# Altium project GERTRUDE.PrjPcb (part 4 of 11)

## Sheet USB.SchDoc: USB
size A3; Author: Silvio Navaretti; CompanyName: ARDUINO; DrawnBy: Silvio Navaretti; Engineer: Silvio Navaretti; Organization: ARDUINO; SheetNumber: 30; SheetTotal: 51; RevAuthor: Silvio Navaretti
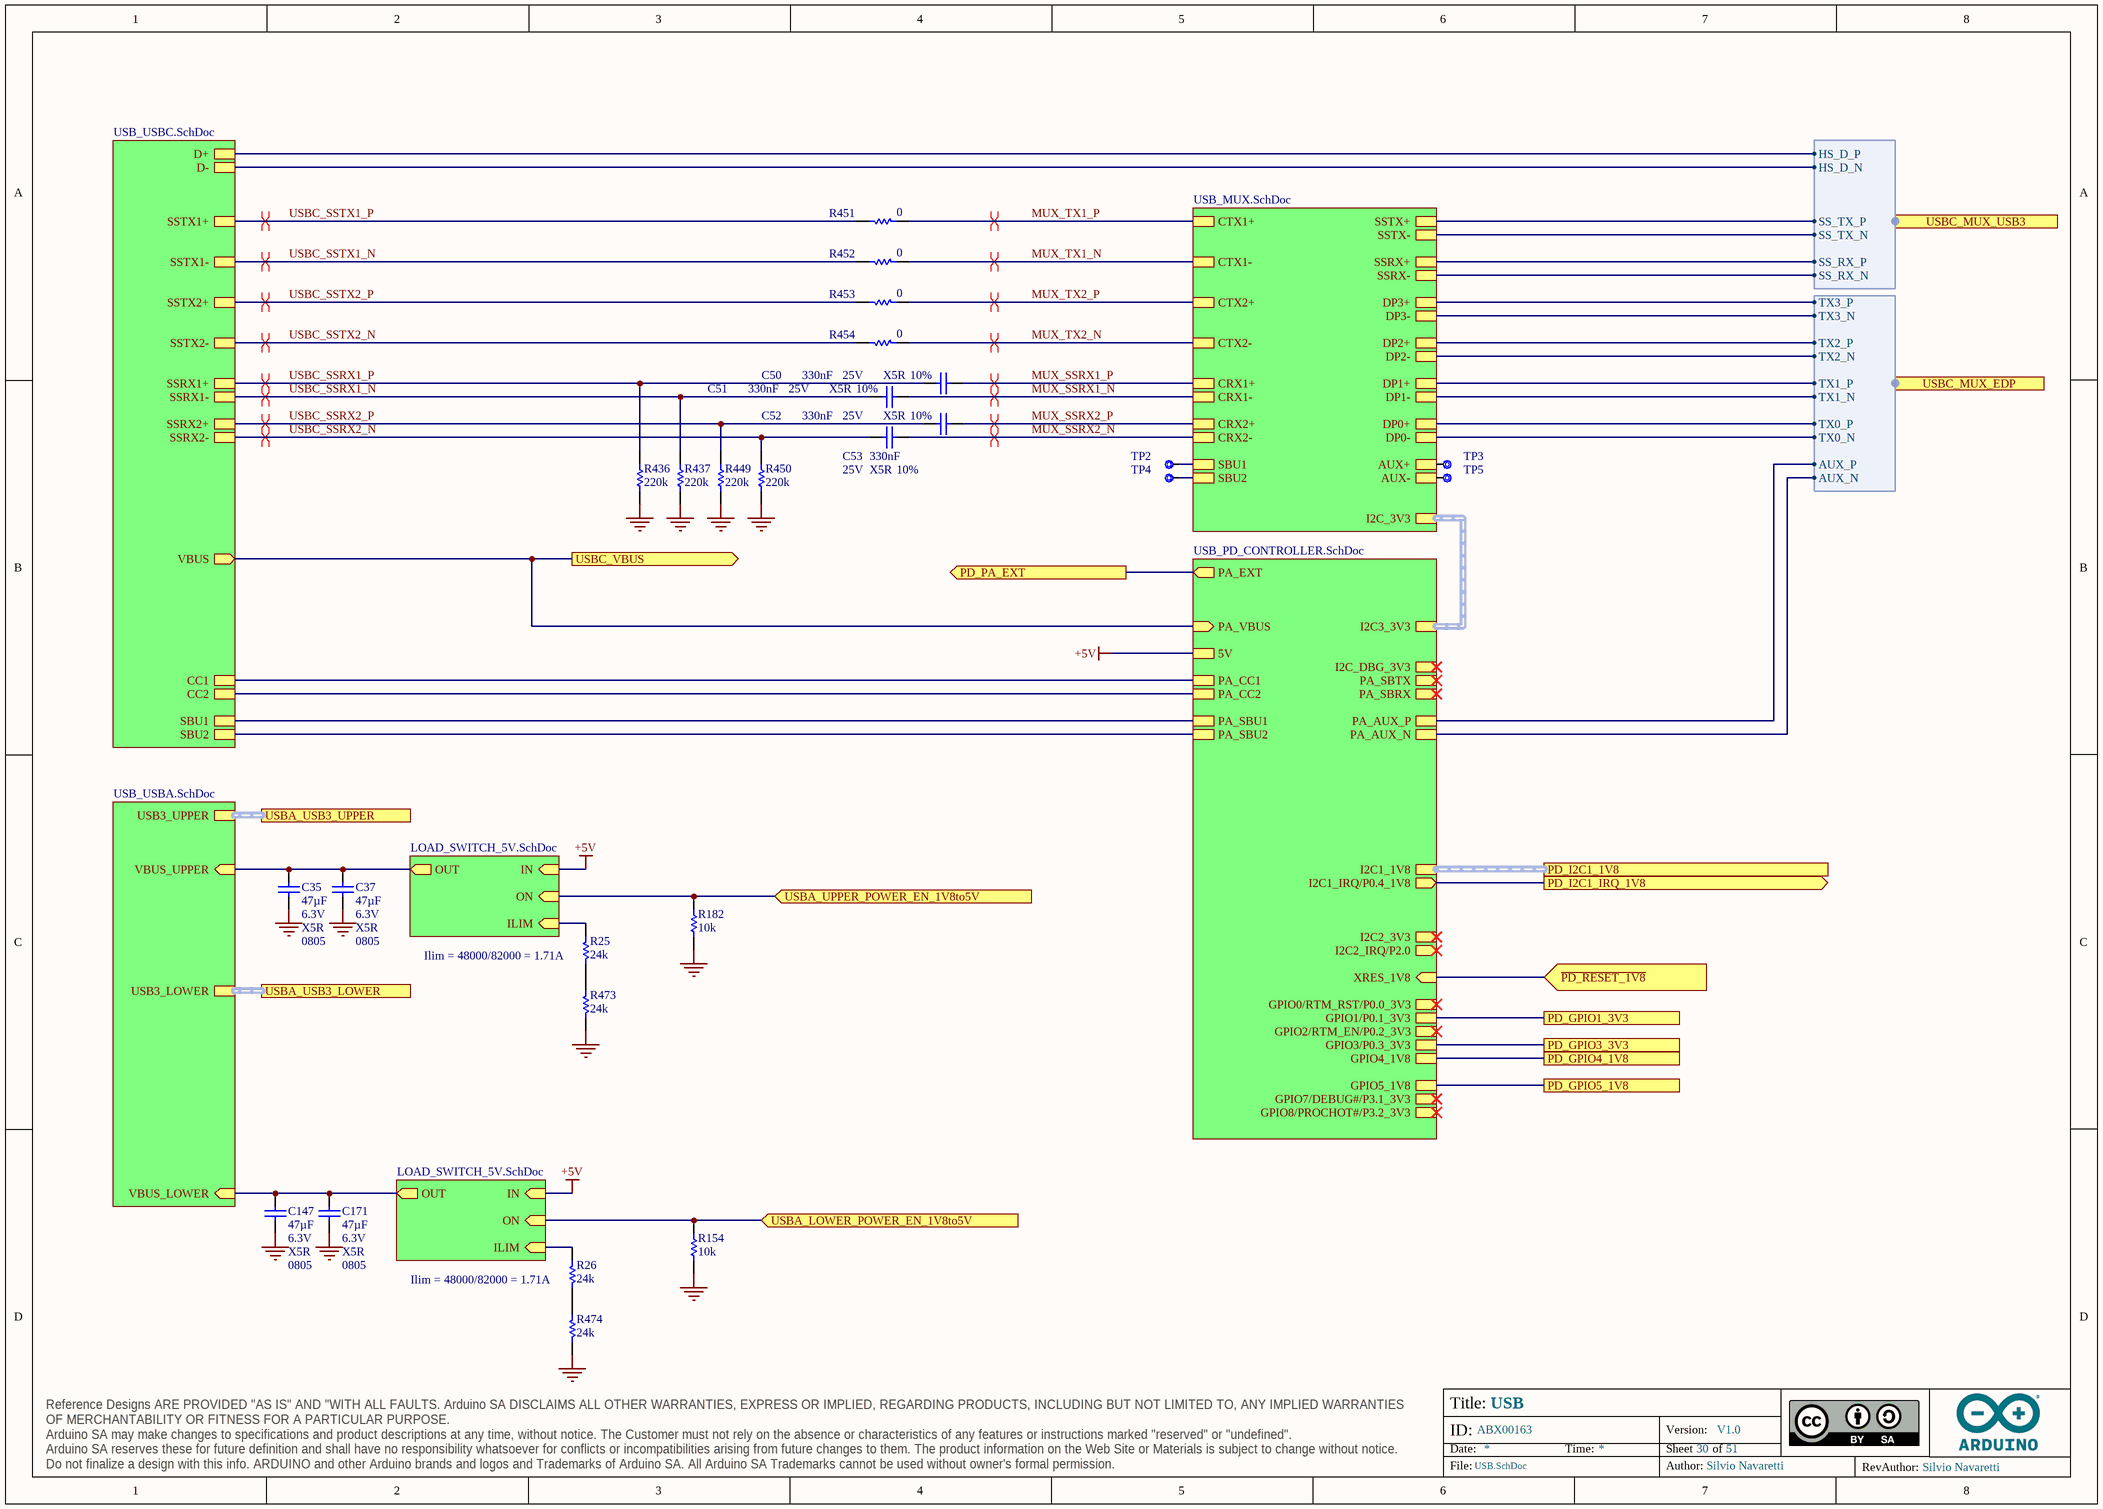
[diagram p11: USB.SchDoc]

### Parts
C35  value 47µF  Voltage: 6.3V  Dielectric: X5R  Case Code (Imperial): 0805  [CAP-0805]  (hidden comment: C0805C476M9PAC7800)
C37  value 47µF  Voltage: 6.3V  Dielectric: X5R  Case Code (Imperial): 0805  [CAP-0805]  (hidden comment: C0805C476M9PAC7800)
C50  value 330nF  Voltage: 25V  Dielectric: X5R  Tolerance: 10%  [CAP-0201]  (hidden comment: CL03A334KA3NRNC)
C51  value 330nF  Voltage: 25V  Dielectric: X5R  Tolerance: 10%  [CAP-0201]  (hidden comment: CL03A334KA3NRNC)
C52  value 330nF  Voltage: 25V  Dielectric: X5R  Tolerance: 10%  [CAP-0201]  (hidden comment: CL03A334KA3NRNC)
C53  value 330nF  Voltage: 25V  Dielectric: X5R  Tolerance: 10%  [CAP-0201]  (hidden comment: CL03A334KA3NRNC)
C147  value 47µF  Voltage: 6.3V  Dielectric: X5R  Case Code (Imperial): 0805  [CAP-0805]  (hidden comment: C0805C476M9PAC7800)
C171  value 47µF  Voltage: 6.3V  Dielectric: X5R  Case Code (Imperial): 0805  [CAP-0805]  (hidden comment: C0805C476M9PAC7800)
R25  value 24k  [RES-0201]  (hidden comment: RC0201FR-0724KL)
R26  value 24k  [RES-0201]  (hidden comment: RC0201FR-0724KL)
R154  value 10k  [RES-0201]  (hidden comment: RC0201FR-0710KL)
R182  value 10k  [RES-0201]  (hidden comment: RC0201FR-0710KL)
R436  value 220k  [RES-0201]  (hidden comment: AC0201FR-07220KL)
R437  value 220k  [RES-0201]  (hidden comment: AC0201FR-07220KL)
R449  value 220k  [RES-0201]  (hidden comment: AC0201FR-07220KL)
R450  value 220k  [RES-0201]  (hidden comment: AC0201FR-07220KL)
R451  value 0  [RES-0201]  (hidden comment: CRCW02010000Z0ED)
R452  value 0  [RES-0201]  (hidden comment: CRCW02010000Z0ED)
R453  value 0  [RES-0201]  (hidden comment: CRCW02010000Z0ED)
R454  value 0  [RES-0201]  (hidden comment: CRCW02010000Z0ED)
R473  value 24k  [RES-0201]  (hidden comment: RC0201FR-0724KL)
R474  value 24k  [RES-0201]  (hidden comment: RC0201FR-0724KL)
TP2  Test point 1.00mm  [TP-1.00MM]  (value not drawn)  (no BOM)
TP3  Test point 1.00mm  [TP-1.00MM]  (value not drawn)  (no BOM)
TP4  Test point 1.00mm  [TP-1.00MM]  (value not drawn)  (no BOM)
TP5  Test point 1.00mm  [TP-1.00MM]  (value not drawn)  (no BOM)

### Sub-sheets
U_LOAD_SWITCH_5V = LOAD_SWITCH_5V.SchDoc: IN (in), OUT (out), ON (in), ILIM (in)
U_LOAD_SWITCH_5V = LOAD_SWITCH_5V.SchDoc: IN (in), OUT (out), ON (in), ILIM (in)
U_USB_MUX = USB_MUX.SchDoc: I2C_3V3 (harness I2C), SSTX-, SSTX+, SBU1, SBU2, SSRX-, SSRX+, DP3+, DP3-, DP2+, DP2-, DP1+, DP1-, DP0+, DP0-, AUX+, AUX-, CTX2+, CTX2-, CRX2+, CRX2-, CRX1+, CRX1-, CTX1+, CTX1-
U_USB_PD_CONTROLLER = USB_PD_CONTROLLER.SchDoc: 5V, PA_VBUS (in), PA_EXT (out), PA_SBU2, PA_SBU1, PA_CC2, PA_CC1, PA_SBTX, PA_SBRX, PA_AUX_P, PA_AUX_N, I2C2_IRQ/P2.0 (out), I2C2_3V3 (harness I2C), I2C3_3V3 (harness I2C), I2C_DBG_3V3 (harness I2C), GPIO0/RTM_RST/P0.0_3V3, GPIO1/P0.1_3V3, GPIO2/RTM_EN/P0.2_3V3, GPIO3/P0.3_3V3, GPIO7/DEBUG#/P3.1_3V3, GPIO8/PROCHOT#/P3.2_3V3, GPIO4_1V8, GPIO5_1V8, I2C1_IRQ/P0.4_1V8 (out), I2C1_1V8 (harness I2C), XRES_1V8 (in)
U_USB_USBA = USB_USBA.SchDoc: VBUS_LOWER (in), USB3_LOWER (harness SOM_MD_USB0), VBUS_UPPER (in), USB3_UPPER (harness SOM_MD_USB0)
U_USB_USBC = USB_USBC.SchDoc: D-, D+, CC1, CC2, SSTX2-, SSTX2+, SSTX1-, SSTX1+, VBUS (out), SBU1, SBU2, SSRX2-, SSRX2+, SSRX1-, SSRX1+

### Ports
PD_GPIO1_3V3, PD_GPIO3_3V3, PD_GPIO4_1V8, PD_GPIO5_1V8, PD_I2C1_1V8 (harness I2C), PD_I2C1_IRQ_1V8 (out), PD_PA_EXT (out), USBA_LOWER_POWER_EN_1V8to5V (in), USBA_UPPER_POWER_EN_1V8to5V (in), USBA_USB3_LOWER (harness SOM_MD_EDP0), USBA_USB3_UPPER (harness SOM_MD_EDP0), USBC_MUX_EDP (harness SOM_MD_EDP0), USBC_MUX_USB3 (harness SOM_MD_USB0), USBC_VBUS (out), ~{PD_RESET_1V8} (in)

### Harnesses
SOM_MD_USB0: SS_TX_N, SS_TX_P, HS_D_P, HS_D_N, SS_RX_P, SS_RX_N
SOM_MD_EDP0: TX0_P, TX1_P, TX2_P, TX3_P, AUX_P, TX0_N, TX1_N, TX2_N, TX3_N, AUX_N

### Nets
+5V: sheet U_USB_PD_CONTROLLER/5V, sheet U_LOAD_SWITCH_5V/IN, sheet U_LOAD_SWITCH_5V/IN
GND: C35.1 C37.1 C147.1 C171.1 R154.1 R182.1 R436.2 R437.2 R449.2 R450.2 R473.1 R474.1
EDP0_AUX_N: sheet U_USB_PD_CONTROLLER/PA_AUX_N, port USBC_MUX_EDP.AUX_N
EDP0_AUX_P: sheet U_USB_PD_CONTROLLER/PA_AUX_P, port USBC_MUX_EDP.AUX_P
EDP0_TX0_N: sheet U_USB_MUX/DP0-, port USBC_MUX_EDP.TX0_N
EDP0_TX0_P: sheet U_USB_MUX/DP0+, port USBC_MUX_EDP.TX0_P
EDP0_TX1_N: sheet U_USB_MUX/DP1-, port USBC_MUX_EDP.TX1_N
EDP0_TX1_P: sheet U_USB_MUX/DP1+, port USBC_MUX_EDP.TX1_P
EDP0_TX2_N: sheet U_USB_MUX/DP2-, port USBC_MUX_EDP.TX2_N
EDP0_TX2_P: sheet U_USB_MUX/DP2+, port USBC_MUX_EDP.TX2_P
EDP0_TX3_N: sheet U_USB_MUX/DP3-, port USBC_MUX_EDP.TX3_N
EDP0_TX3_P: sheet U_USB_MUX/DP3+, port USBC_MUX_EDP.TX3_P
MD_GPIO_3: port PD_I2C1_IRQ_1V8, sheet U_USB_PD_CONTROLLER/I2C1_IRQ/P0.4_1V8
MD_GPIO_48: port PD_GPIO5_1V8, sheet U_USB_PD_CONTROLLER/GPIO5_1V8
MD_GPIO_94: port PD_GPIO4_1V8, sheet U_USB_PD_CONTROLLER/GPIO4_1V8
MD_GPIO_104: port ~{PD_RESET_1V8}, sheet U_USB_PD_CONTROLLER/XRES_1V8
MD_USB0_3.1.HS_D_N: sheet U_USB_USBC/D-, port USBC_MUX_USB3.HS_D_N
MD_USB0_3.1.HS_D_P: sheet U_USB_USBC/D+, port USBC_MUX_USB3.HS_D_P
MD_USB0_3.1.SS_RX_N: sheet U_USB_MUX/SSRX-, port USBC_MUX_USB3.SS_RX_N
MD_USB0_3.1.SS_RX_P: sheet U_USB_MUX/SSRX+, port USBC_MUX_USB3.SS_RX_P
MD_USB0_3.1.SS_TX_N: sheet U_USB_MUX/SSTX-, port USBC_MUX_USB3.SS_TX_N
MD_USB0_3.1.SS_TX_P: sheet U_USB_MUX/SSTX+, port USBC_MUX_USB3.SS_TX_P
MUX_SSRX1_N: C51.1 ; sheet U_USB_MUX/CRX1-
MUX_SSRX1_P: C50.1 ; sheet U_USB_MUX/CRX1+
MUX_SSRX2_N: C53.1 ; sheet U_USB_MUX/CRX2-
MUX_SSRX2_P: C52.1 ; sheet U_USB_MUX/CRX2+
MUX_TX1_N: R452.2 ; sheet U_USB_MUX/CTX1-
MUX_TX1_P: R451.2 ; sheet U_USB_MUX/CTX1+
MUX_TX2_N: R454.2 ; sheet U_USB_MUX/CTX2-
MUX_TX2_P: R453.2 ; sheet U_USB_MUX/CTX2+
PA_VBUS: port USBC_VBUS, sheet U_USB_USBC/VBUS, sheet U_USB_PD_CONTROLLER/PA_VBUS
USBC_CC1: sheet U_USB_USBC/CC1, sheet U_USB_PD_CONTROLLER/PA_CC1
USBC_CC2: sheet U_USB_USBC/CC2, sheet U_USB_PD_CONTROLLER/PA_CC2
USBC_SBU1: sheet U_USB_USBC/SBU1, sheet U_USB_PD_CONTROLLER/PA_SBU1
USBC_SBU2: sheet U_USB_USBC/SBU2, sheet U_USB_PD_CONTROLLER/PA_SBU2
USBC_SSRX1_N: C51.2 R437.1 ; sheet U_USB_USBC/SSRX1-
USBC_SSRX1_P: C50.2 R436.1 ; sheet U_USB_USBC/SSRX1+
USBC_SSRX2_N: C53.2 R450.1 ; sheet U_USB_USBC/SSRX2-
USBC_SSRX2_P: C52.2 R449.1 ; sheet U_USB_USBC/SSRX2+
USBC_SSTX1_N: R452.1 ; sheet U_USB_USBC/SSTX1-
USBC_SSTX1_P: R451.1 ; sheet U_USB_USBC/SSTX1+
USBC_SSTX2_N: R454.1 ; sheet U_USB_USBC/SSTX2-
USBC_SSTX2_P: R453.1 ; sheet U_USB_USBC/SSTX2+
NetC35_2: C35.2 C37.2 ; sheet U_USB_USBA/VBUS_UPPER, sheet U_LOAD_SWITCH_5V/OUT
NetC147_2: C147.2 C171.2 ; sheet U_USB_USBA/VBUS_LOWER, sheet U_LOAD_SWITCH_5V/OUT
NetQ3_2: port PD_GPIO3_3V3, sheet U_USB_PD_CONTROLLER/GPIO3/P0.3_3V3
NetQ3_3: port PD_GPIO1_3V3, sheet U_USB_PD_CONTROLLER/GPIO1/P0.1_3V3
NetR25_1: R25.1 R473.2
NetR25_2: R25.2 ; sheet U_LOAD_SWITCH_5V/ILIM
NetR26_1: R26.1 R474.2
NetR26_2: R26.2 ; sheet U_LOAD_SWITCH_5V/ILIM
NetR154_2: R154.2 ; port USBA_LOWER_POWER_EN_1V8to5V, sheet U_LOAD_SWITCH_5V/ON
NetR182_2: R182.2 ; port USBA_UPPER_POWER_EN_1V8to5V, sheet U_LOAD_SWITCH_5V/ON
NetR215_1: port PD_PA_EXT, sheet U_USB_PD_CONTROLLER/PA_EXT
NetTP2_X: TP2.X ; sheet U_USB_MUX/SBU1
NetTP3_X: TP3.X ; sheet U_USB_MUX/AUX+
NetTP4_X: TP4.X ; sheet U_USB_MUX/SBU2
NetTP5_X: TP5.X ; sheet U_USB_MUX/AUX-

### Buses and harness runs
harness port PD_I2C1_1V8 = sheet U_USB_PD_CONTROLLER/I2C1_1V8
harness port USBA_USB3_LOWER = sheet U_USB_USBA/USB3_LOWER
harness port USBA_USB3_UPPER = sheet U_USB_USBA/USB3_UPPER
harness sheet U_USB_MUX/I2C_3V3 = sheet U_USB_PD_CONTROLLER/I2C3_3V3

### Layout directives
differential pair; differential pair class DIFF_MUX_USBC; net class NET_DIFF_USBC: MUX_SSRX1_N, MUX_SSRX1_P, MUX_SSRX2_N, MUX_SSRX2_P, MUX_TX1_N, MUX_TX1_P, MUX_TX2_N, MUX_TX2_P
differential pair; differential pair class DIFF_MUXCAPS_USBC; net class NET_DIFF_USB: USBC_SSRX1_N, USBC_SSRX1_P, USBC_SSRX2_N, USBC_SSRX2_P, USBC_SSTX1_N, USBC_SSTX1_P, USBC_SSTX2_N, USBC_SSTX2_P

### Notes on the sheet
- (near R25) Ilim = 48000/82000 = 1.71A
- (near R26) Ilim = 48000/82000 = 1.71A

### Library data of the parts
C35 C37 C147 C171 = C0199-A.1: CAP CHIP 0805 47uF 20% 6.3V X5R; Manufacturer: KEMET; Code Arduino: C0199
C50-C53 = C0201-A.1: CAP CHIP 0201 330nF 10% 25V X5R; Manufacturer: Samsung Electro-Mechanics; Code Arduino: C0201
R25 R26 R473 R474 = R0398-A.1: RES CHIP 0201 24k 1% 1/20W; Manufacturer: YAGEO; Power: 50mW; Code Arduino: R0398; Temperature Coefficient: 200ppm
R154 R182 = R0145-A.21: RES CHIP 0201 10k 1% 1/20W; Manufacturer: Yageo; Power: 50mW; Temperature coefficient: 200ppm; Code Arduino: R0145
R436 R437 R449 R450 = R0199-A.20: RES CHIP 0201 220k 1% 1/20W; Manufacturer: Yageo; Temperature coefficient: 200ppm; Power: 50mW; Code Arduino: R0199
R451-R454 = R0140-A.21: RES CHIP 0201 0R; Manufacturer: Vishay; Tolerance: 0%; Code Arduino: R0140; Temperature coefficient: 0ppm; Power: 50mW
TP2-TP5 = UT0013-A.6: Part Number: This is not a component

## Sheet USB_USBC.SchDoc: USBC
size A3; Author: Silvio Navaretti; CompanyName: ARDUINO; DrawnBy: Silvio Navaretti; Engineer: Silvio Navaretti; Organization: ARDUINO; SheetNumber: 31; SheetTotal: 51; RevAuthor: Silvio Navaretti
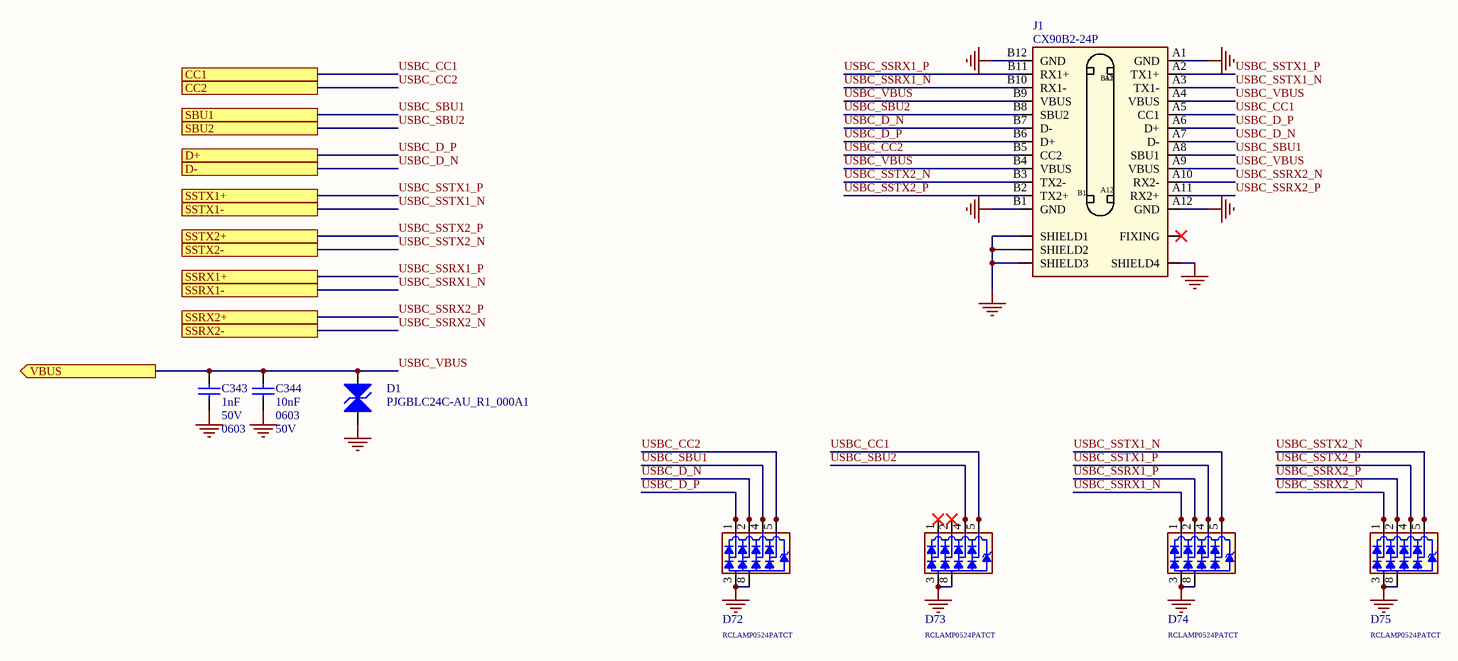
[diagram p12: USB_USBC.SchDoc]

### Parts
C343  value 1nF  Voltage: 50V  Case Code (Imperial): 0603  [CAP-0603]  (hidden comment: CL10B102KB8WPNC)
C344  value 10nF  Case Code (Imperial): 0603  Voltage: 50V  [CAP-0603]  (hidden comment: 0603B103K500CT)
D1  PJGBLC24C-AU_R1_000A1  [SOD323 NO POLARITY]
D72  RCLAMP0524PATCT  [SLP2510P8]
D73  RCLAMP0524PATCT  [SLP2510P8]
D74  RCLAMP0524PATCT  [SLP2510P8]
D75  RCLAMP0524PATCT  [SLP2510P8]
J1  CX90B2-24P  [CX90B2-24P]

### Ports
CC1, CC2, D+, D-, SBU1, SBU2, SSRX1+, SSRX1-, SSRX2+, SSRX2-, SSTX1+, SSTX1-, SSTX2+, SSTX2-, VBUS (out)

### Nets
GND: C343.2 C344.2 D1.1(A1) D72.3 D72.8 D73.3 D73.8 D74.3 D74.8 D75.3 D75.8 J1.A1(GND) J1.A12(GND) J1.B1(GND) J1.B12(GND) J1.SHIELD1 J1.SHIELD2 J1.SHIELD3 J1.SHIELD4
USBC_CC1: D73.5 D73.6 J1.A5(CC1) ; port CC1
USBC_CC2: D72.5 D72.6 J1.B5(CC2) ; port CC2
USBC_D_N: D72.2 D72.9 J1.A7(D-) J1.B7(D-) ; port D-  [project net MD_USB0_3.1.HS_D_N]
USBC_D_P: D72.1 D72.10 J1.A6(D+) J1.B6(D+) ; port D+  [project net MD_USB0_3.1.HS_D_P]
USBC_SBU1: D72.4 D72.7 J1.A8(SBU1) ; port SBU1
USBC_SBU2: D73.4 D73.7 J1.B8(SBU2) ; port SBU2
USBC_SSRX1_N: D74.1 D74.10 J1.B10(RX1-) ; port SSRX1-
USBC_SSRX1_P: D74.2 D74.9 J1.B11(RX1+) ; port SSRX1+
USBC_SSRX2_N: D75.1 D75.10 J1.A10(RX2-) ; port SSRX2-
USBC_SSRX2_P: D75.2 D75.9 J1.A11(RX2+) ; port SSRX2+
USBC_SSTX1_N: D74.5 D74.6 J1.A3(TX1-) ; port SSTX1-
USBC_SSTX1_P: D74.4 D74.7 J1.A2(TX1+) ; port SSTX1+
USBC_SSTX2_N: D75.5 D75.6 J1.B3(TX2-) ; port SSTX2-
USBC_SSTX2_P: D75.4 D75.7 J1.B2(TX2+) ; port SSTX2+
USBC_VBUS: C343.1 C344.1 D1.2(A2) J1.A4(VBUS) J1.A9(VBUS) J1.B4(VBUS) J1.B9(VBUS) ; port VBUS  [project net PA_VBUS]
NetD73_1: D73.1 D73.10
NetD73_2: D73.2 D73.9

Not connected (* = marked no-connect by the designer): J1 FIXING*

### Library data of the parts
C343 = C0063-A.3: CAP CHIP 0603 1nF 10% 50V X7R; Manufacturer: Samsung Electro-Mechanics; Code Arduino: C0063
C344 = C0040-A.14: CAP CHIP 0603 10nF 10% 50V X7R; Manufacturer: Walsin; Code Arduino: 0142
D1 = D0098-A.2: TVS BIDIRECTIONAL SMD Vr 24V, Vbr min 27.27V, 350W, SOD-323; V(BR) Typ (V): 26.7; Code Arduino: D0098
D72-D75 = D0097-A.6: TVS UNIDIRECTIONAL 4CH 0.8pF 5V SLP2510P8 10-pin 2.5x1.0x0.58mm; Manufacturer: SEMTECH; Code Arduino: D0097; Device Type: ESD protection
J1 = J0010-A.12: CONN RCPT USB3.1 TYPEC 24POS SMD; Manufacturer: Hirose; Code Arduino: A5518; Gender: Receptacle; Connector Type: USB

## Sheet USB_MUX.SchDoc: USB MUX
size A3; Author: Silvio Navaretti; CompanyName: ARDUINO; DrawnBy: Silvio Navaretti; Engineer: Silvio Navaretti; Organization: ARDUINO; SheetNumber: 32; SheetTotal: 51; RevAuthor: Silvio Navaretti
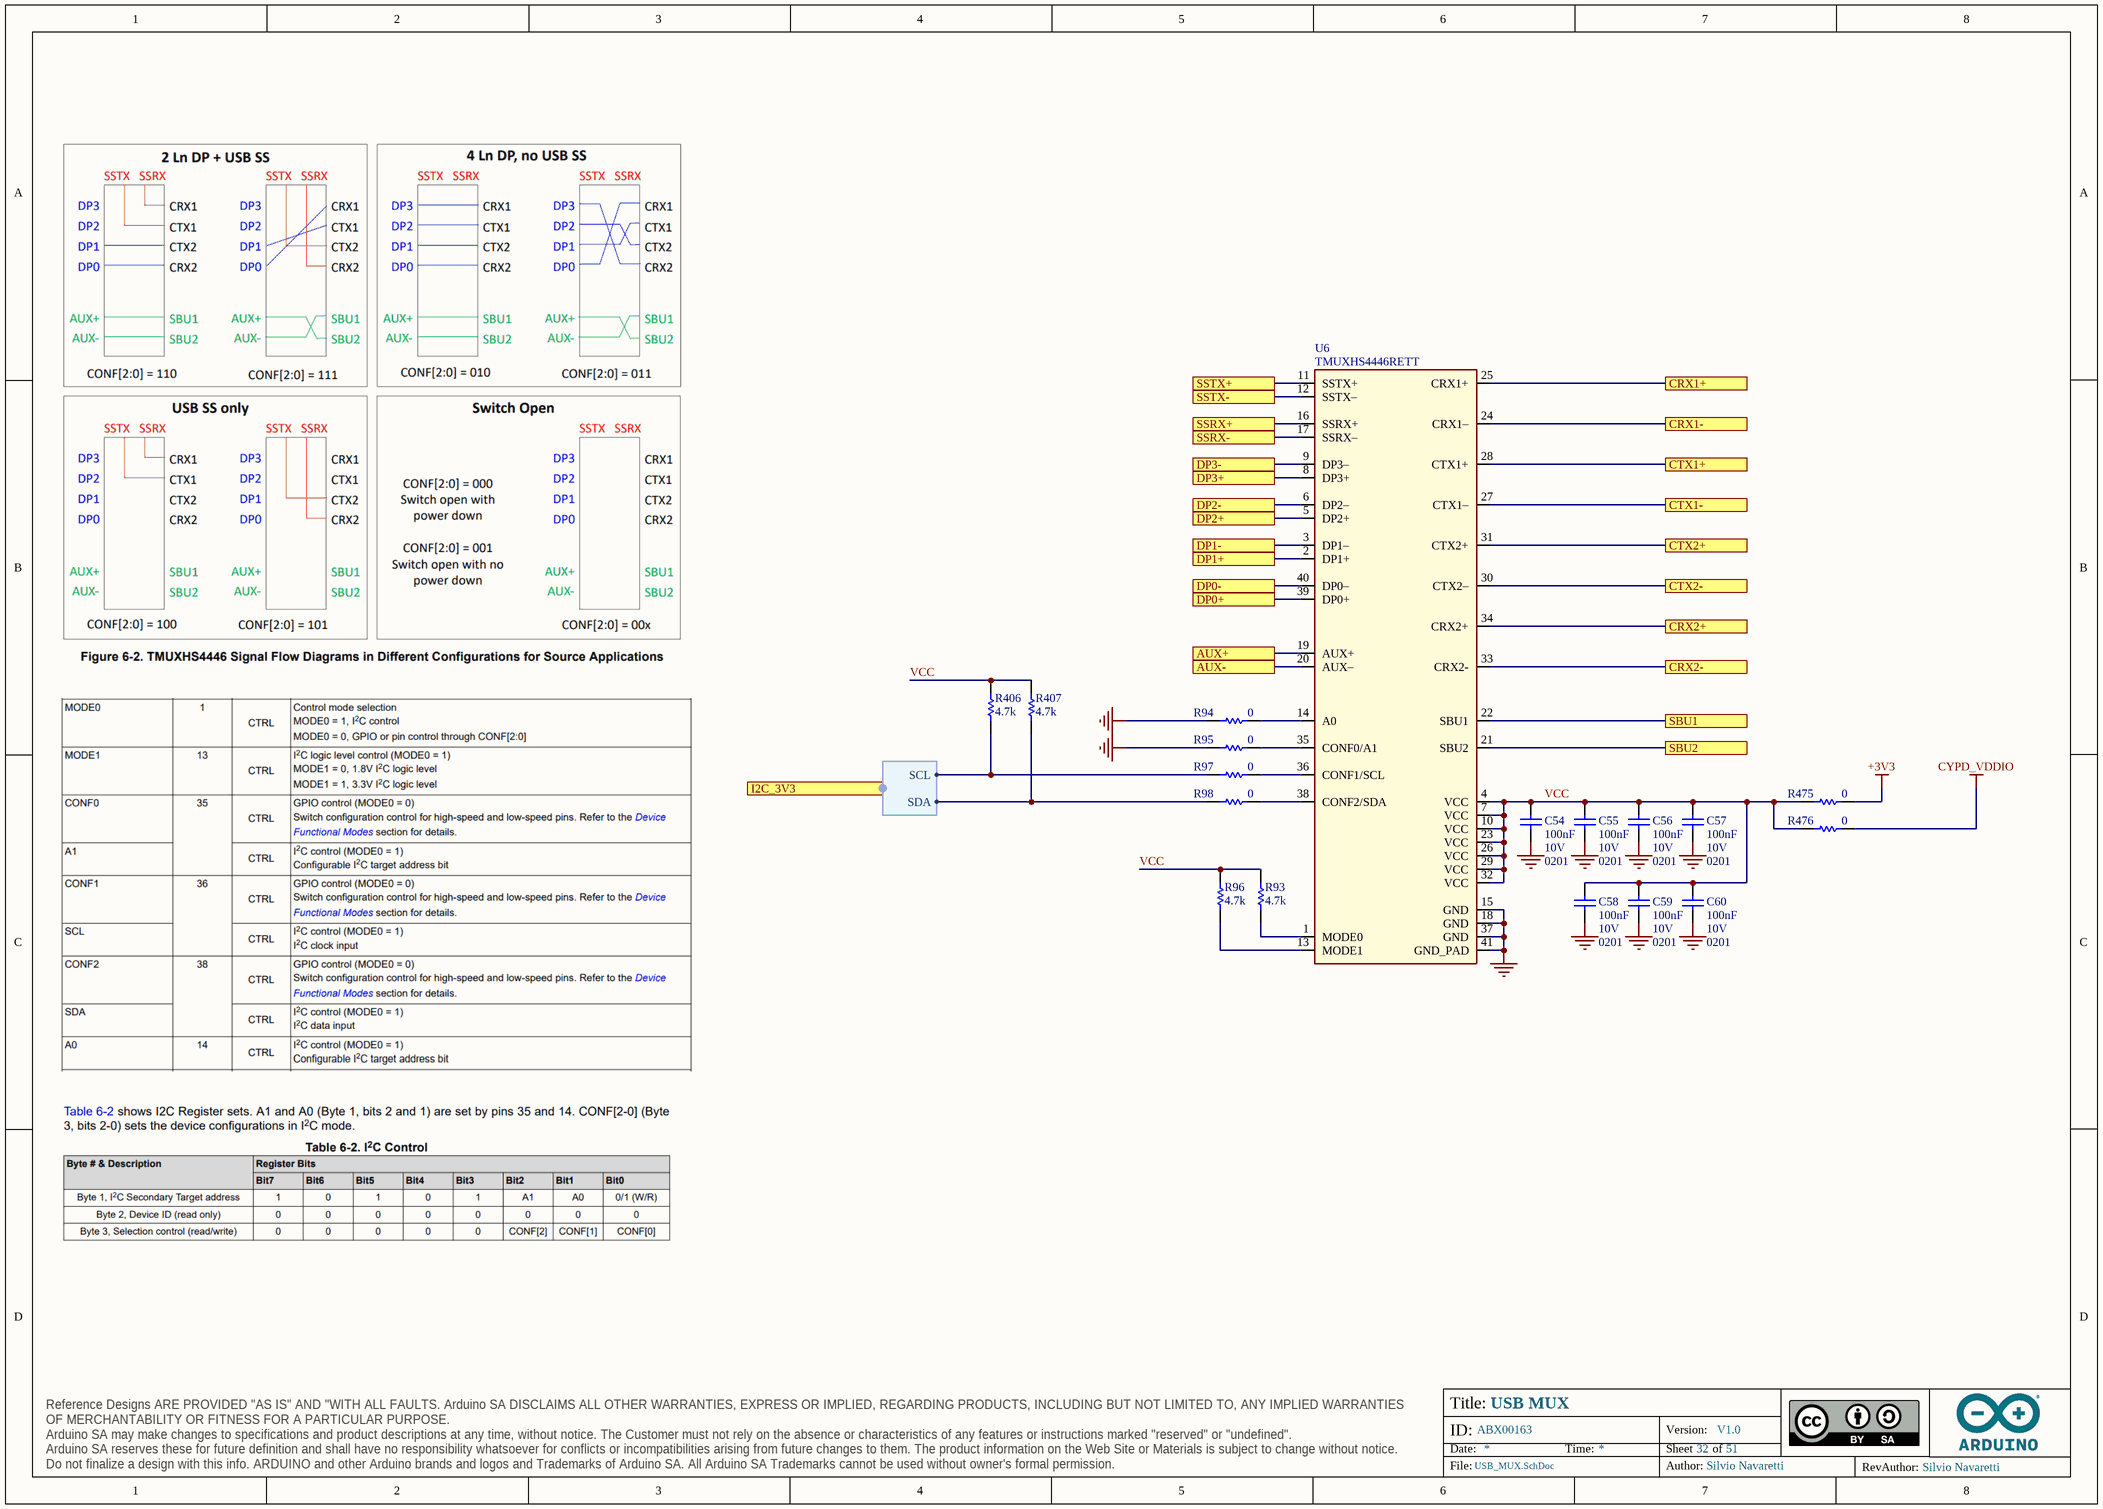
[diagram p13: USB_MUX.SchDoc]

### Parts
C54  value 100nF  Voltage: 10V  Case Code (Imperial): 0201  [CAP-0201]  (hidden comment: CL03A104KP3NNNC)
C55  value 100nF  Voltage: 10V  Case Code (Imperial): 0201  [CAP-0201]  (hidden comment: CL03A104KP3NNNC)
C56  value 100nF  Voltage: 10V  Case Code (Imperial): 0201  [CAP-0201]  (hidden comment: CL03A104KP3NNNC)
C57  value 100nF  Voltage: 10V  Case Code (Imperial): 0201  [CAP-0201]  (hidden comment: CL03A104KP3NNNC)
C58  value 100nF  Voltage: 10V  Case Code (Imperial): 0201  [CAP-0201]  (hidden comment: CL03A104KP3NNNC)
C59  value 100nF  Voltage: 10V  Case Code (Imperial): 0201  [CAP-0201]  (hidden comment: CL03A104KP3NNNC)
C60  value 100nF  Voltage: 10V  Case Code (Imperial): 0201  [CAP-0201]  (hidden comment: CL03A104KP3NNNC)
R93  value 4.7k  [RES-0201]  (hidden comment: RC0201FR-074K7L)
R94  value 0  [RES-0201]  (hidden comment: CRCW02010000Z0ED)
R95  value 0  [RES-0201]  (hidden comment: CRCW02010000Z0ED)
R96  value 4.7k  [RES-0201]  (hidden comment: RC0201FR-074K7L)
R97  value 0  [RES-0201]  (hidden comment: CRCW02010000Z0ED)
R98  value 0  [RES-0201]  (hidden comment: CRCW02010000Z0ED)
R406  value 4.7k  [RES-0201]  (hidden comment: RC0201FR-074K7L)
R407  value 4.7k  [RES-0201]  (hidden comment: RC0201FR-074K7L)
R475  value 0  [RES-0201]  (hidden comment: CRCW02010000Z0ED)
R476  value 0  [RES-0201]  (hidden comment: CRCW02010000Z0ED)
U6  TMUXHS4446RETT  [TI QWFN40 RET0040A Pitch 0.4mm 3x6mm]

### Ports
AUX+, AUX-, CRX1+, CRX1-, CRX2+, CRX2-, CTX1+, CTX1-, CTX2+, CTX2-, DP0+, DP0-, DP1+, DP1-, DP2+, DP2-, DP3+, DP3-, I2C_3V3 (harness I2C), SBU1, SBU2, SSRX+, SSRX-, SSTX+, SSTX-

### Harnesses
I2C: SDA, SCL

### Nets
+3V3: R475.2
CYPD_VDDIO: R476.2
GND: C54.1 C55.1 C56.1 C57.1 C58.1 C59.1 C60.1 R94.1 R95.1 U6.15(GND) U6.18(GND) U6.37(GND) U6.41(GND_PAD)
EDP0_TX0_N: U6.40(DP0–) ; port DP0-
EDP0_TX0_P: U6.39(DP0+) ; port DP0+
EDP0_TX1_N: U6.3(DP1–) ; port DP1-
EDP0_TX1_P: U6.2(DP1+) ; port DP1+
EDP0_TX2_N: U6.6(DP2–) ; port DP2-
EDP0_TX2_P: U6.5(DP2+) ; port DP2+
EDP0_TX3_N: U6.9(DP3–) ; port DP3-
EDP0_TX3_P: U6.8(DP3+) ; port DP3+
MD_USB0_3.1.SS_RX_N: U6.17(SSRX–) ; port SSRX-
MD_USB0_3.1.SS_RX_P: U6.16(SSRX+) ; port SSRX+
MD_USB0_3.1.SS_TX_N: U6.12(SSTX–) ; port SSTX-
MD_USB0_3.1.SS_TX_P: U6.11(SSTX+) ; port SSTX+
MUX_SSRX1_N: U6.24(CRX1–) ; port CRX1-
MUX_SSRX1_P: U6.25(CRX1+) ; port CRX1+
MUX_SSRX2_N: U6.33(CRX2-) ; port CRX2-
MUX_SSRX2_P: U6.34(CRX2+) ; port CRX2+
MUX_TX1_N: U6.27(CTX1–) ; port CTX1-
MUX_TX1_P: U6.28(CTX1+) ; port CTX1+
MUX_TX2_N: U6.30(CTX2–) ; port CTX2-
MUX_TX2_P: U6.31(CTX2+) ; port CTX2+
VCC: C54.2 C55.2 C56.2 C57.2 C58.2 C59.2 C60.2 R93.1 R96.1 R406.1 R407.1 R475.1 R476.1 U6.4(VCC) U6.7(VCC) U6.10(VCC) U6.23(VCC) U6.26(VCC) U6.29(VCC) U6.32(VCC)  [project net VCC_32]
NetR93_2: R93.2 U6.1(MODE0)
NetR94_2: R94.2 U6.14(A0)
NetR95_2: R95.2 U6.35(CONF0/A1)
NetR96_2: R96.2 U6.13(MODE1)
NetR97_1: R97.1 R406.2 ; port I2C_3V3.SCL
NetR97_2: R97.2 U6.36(CONF1/SCL)
NetR98_1: R98.1 R407.2 ; port I2C_3V3.SDA
NetR98_2: R98.2 U6.38(CONF2/SDA)
NetTP2_X: U6.22(SBU1) ; port SBU1
NetTP3_X: U6.19(AUX+) ; port AUX+
NetTP4_X: U6.21(SBU2) ; port SBU2
NetTP5_X: U6.20(AUX–) ; port AUX-

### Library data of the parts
C54-C60 = C0113-A.6: CAP CHIP 0201 100nF 10% 10V X5R; Manufacturer: Samsung Electro-Mechanics; Code Arduino: C0113
R93 R96 R406 R407 = R0151-A.21: RES CHIP 0201 4k7 1% 1/20W; Manufacturer: Yageo; Temperature coefficient: 200ppm; Power: 50mW; Code Arduino: A5521
R94 R95 R97 R98 R475 R476 = R0140-A.21: RES CHIP 0201 0R; Manufacturer: Vishay; Temperature coefficient: 0ppm; Code Arduino: R0140; Power: 50mW; Tolerance: 0%
U6 = U0499-A.3: IC MUX Alt Mode Crossbar USB-C 10Gbps, QFN40 3x6mm; Manufacturer: Texas Instruments; Code Arduino: U0499

## Sheet USB_PD_CONTROLLER.SchDoc: USB PD CONTROLLER
size A3; Author: Silvio Navaretti; CompanyName: ARDUINO; DrawnBy: Silvio Navaretti; Engineer: Silvio Navaretti; Organization: ARDUINO; SheetNumber: 33; SheetTotal: 51; RevAuthor: Silvio Navaretti
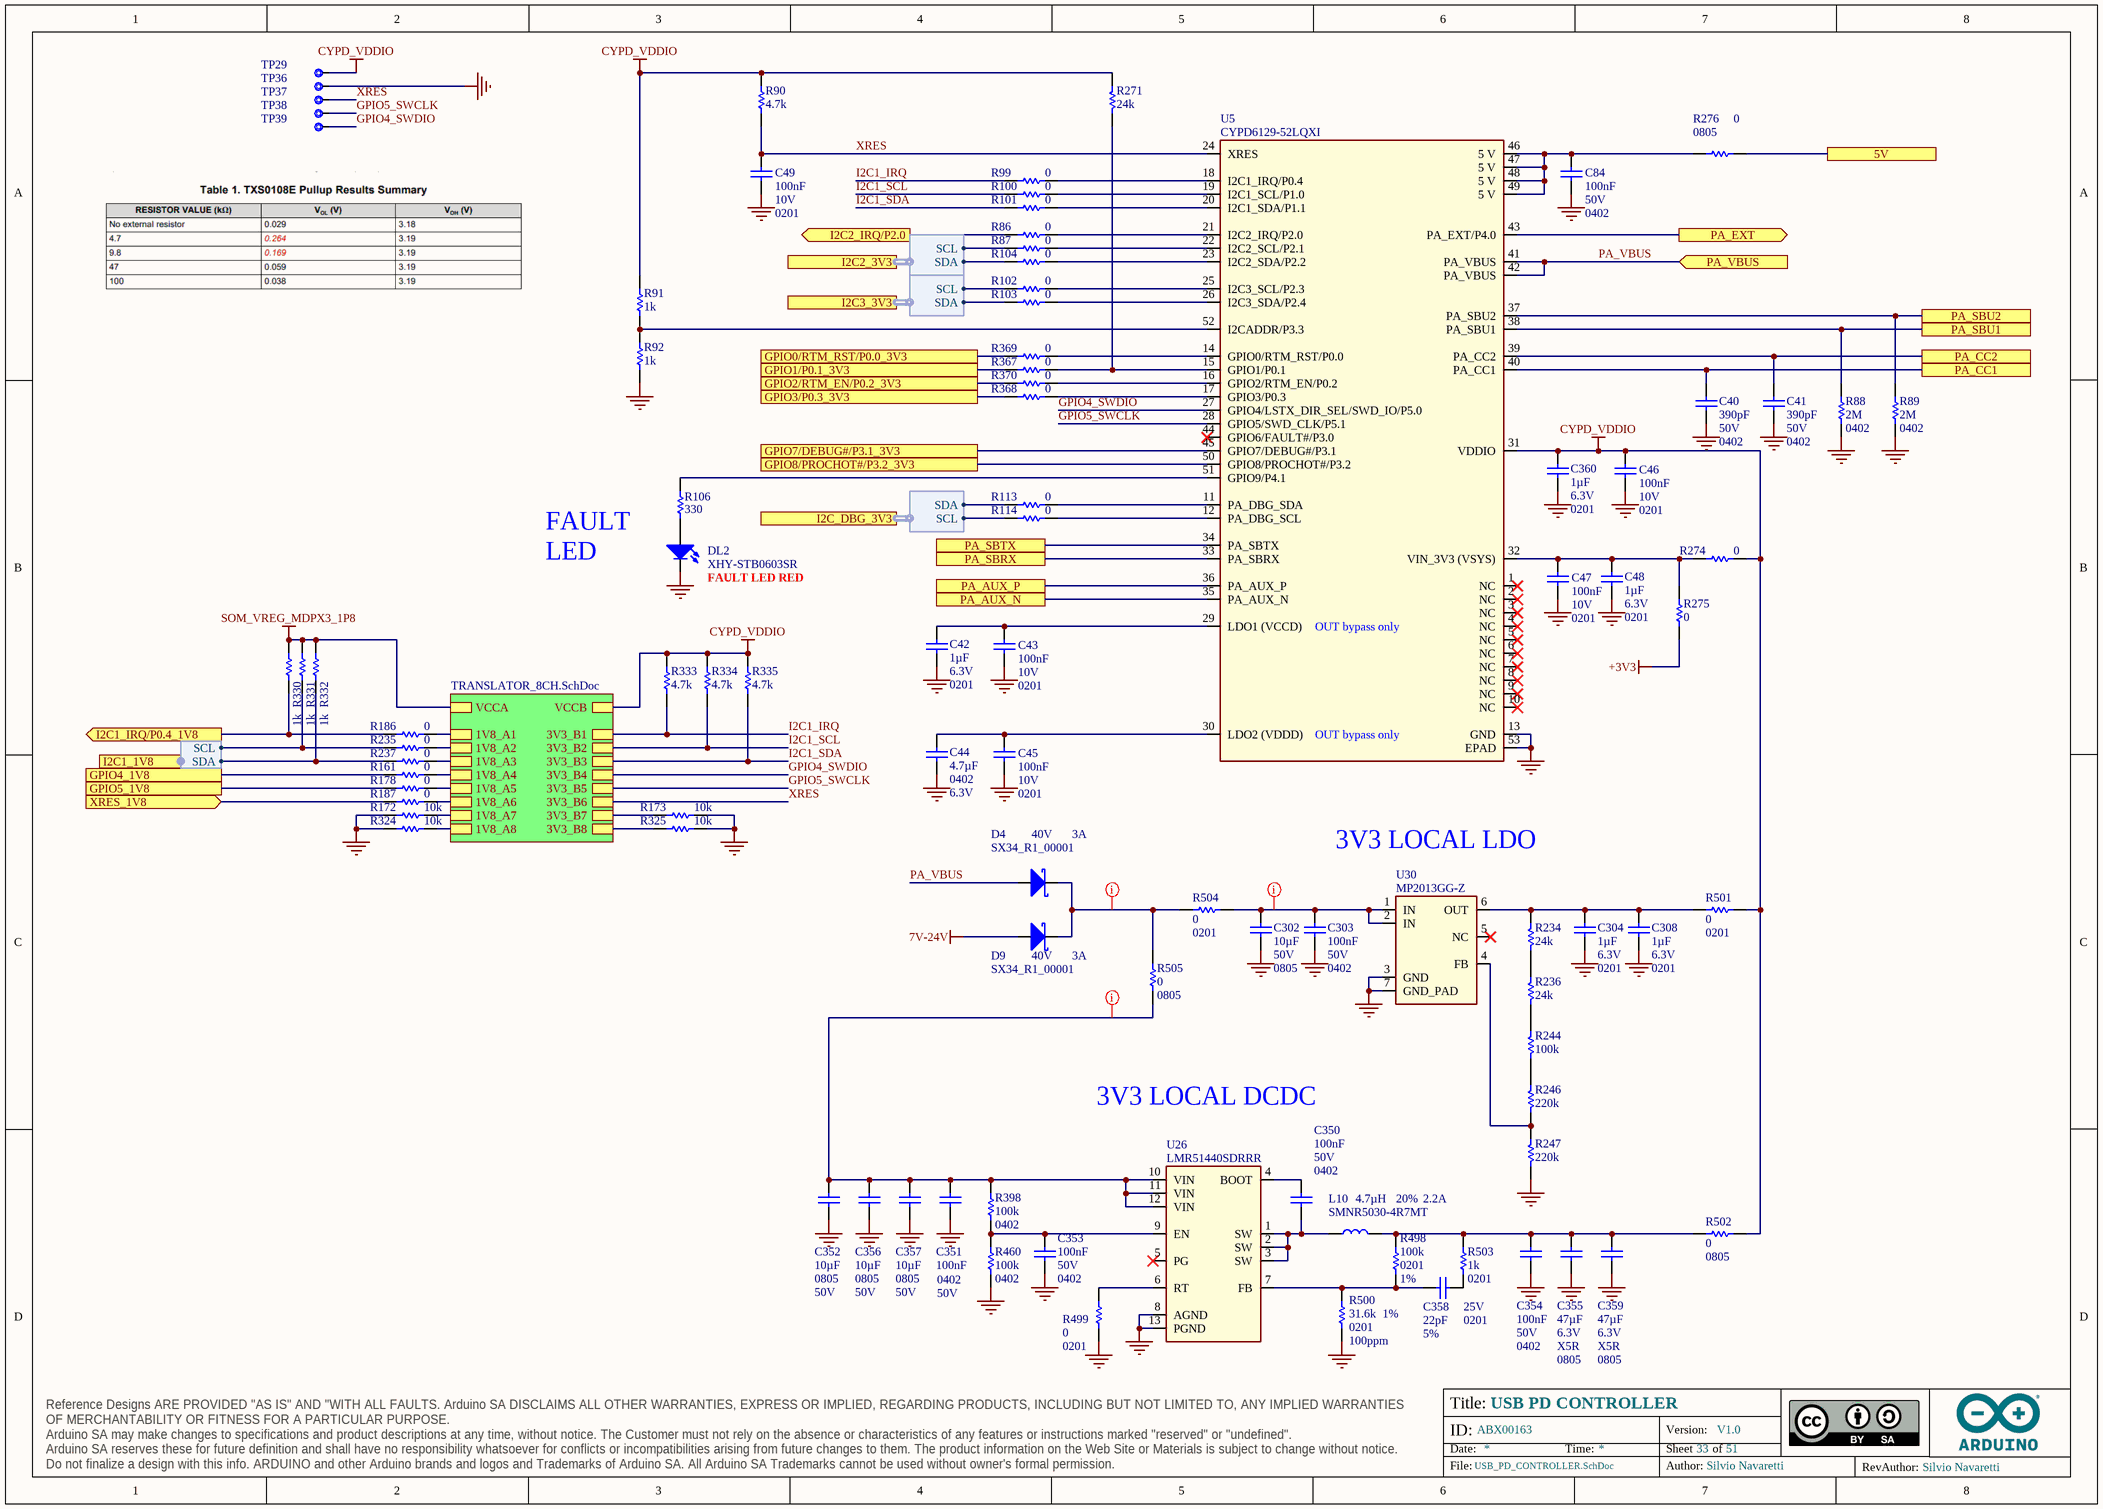
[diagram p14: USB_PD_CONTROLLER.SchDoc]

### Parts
C40  value 390pF  Voltage: 50V  Case Code (Imperial): 0402  [CAP-0402]  (hidden comment: CL05B391KB5NNNC)
C41  value 390pF  Voltage: 50V  Case Code (Imperial): 0402  [CAP-0402]  (hidden comment: CL05B391KB5NNNC)
C42  value 1µF  Voltage: 6.3V  Case Code (Imperial): 0201  [CAP-0201]  (hidden comment: GRM033R60J105MEA2D)
C43  value 100nF  Voltage: 10V  Case Code (Imperial): 0201  [CAP-0201]  (hidden comment: CL03A104KP3NNNC)
C44  value 4.7µF  Case Code (Imperial): 0402  Voltage: 6.3V  [CAP-0402]  (hidden comment: C1005A475M6R3NT)
C45  value 100nF  Voltage: 10V  Case Code (Imperial): 0201  [CAP-0201]  (hidden comment: CL03A104KP3NNNC)
C46  value 100nF  Voltage: 10V  Case Code (Imperial): 0201  [CAP-0201]  (hidden comment: CL03A104KP3NNNC)
C47  value 100nF  Voltage: 10V  Case Code (Imperial): 0201  [CAP-0201]  (hidden comment: CL03A104KP3NNNC)
C48  value 1µF  Voltage: 6.3V  Case Code (Imperial): 0201  [CAP-0201]  (hidden comment: GRM033R60J105MEA2D)
C49  value 100nF  Voltage: 10V  Case Code (Imperial): 0201  [CAP-0201]  (hidden comment: CL03A104KP3NNNC)
C84  value 100nF  Voltage: 50V  Case Code (Imperial): 0402  [CAP-0402]  (hidden comment: GRM155R61H104KE19D)
C302  value 10µF  Voltage: 50V  Case Code (Imperial): 0805  [CAP-0805]  (hidden comment: GRM21BR61H106ME43L)
C303  value 100nF  Voltage: 50V  Case Code (Imperial): 0402  [CAP-0402]  (hidden comment: GRM155R61H104KE19D)
C304  value 1µF  Voltage: 6.3V  Case Code (Imperial): 0201  [CAP-0201]  (hidden comment: GRM033R60J105MEA2D)
C308  value 1µF  Voltage: 6.3V  Case Code (Imperial): 0201  [CAP-0201]  (hidden comment: GRM033R60J105MEA2D)
C350  value 100nF  Voltage: 50V  Case Code (Imperial): 0402  [CAP-0402]  (hidden comment: GRM155R61H104KE19D)
C351  value 100nF  Voltage: 50V  Case Code (Imperial): 0402  [CAP-0402]  (hidden comment: GRM155R61H104KE19D)
C352  value 10µF  Case Code (Imperial): 0805  Voltage: 50V  [CAP-0805]  (hidden comment: GRM21BR61H106ME43L)
C353  value 100nF  Voltage: 50V  Case Code (Imperial): 0402  [CAP-0402]  (hidden comment: GRM155R61H104KE19D)
C354  value 100nF  Voltage: 50V  Case Code (Imperial): 0402  [CAP-0402]  (hidden comment: GRM155R61H104KE19D)
C355  value 47µF  Voltage: 6.3V  Dielectric: X5R  Case Code (Imperial): 0805  [CAP-0805]  (hidden comment: C0805C476M9PAC7800)
C356  value 10µF  Case Code (Imperial): 0805  Voltage: 50V  [CAP-0805]  (hidden comment: GRM21BR61H106ME43L)
C357  value 10µF  Case Code (Imperial): 0805  Voltage: 50V  [CAP-0805]  (hidden comment: GRM21BR61H106ME43L)
C358  value 22pF  Tolerance: 5%  Case Code (Imperial): 0201  Voltage: 25V  [CAP-0201]  (hidden comment: CC0201JPNPO8BN220)
C359  value 47µF  Voltage: 6.3V  Dielectric: X5R  Case Code (Imperial): 0805  [CAP-0805]  (hidden comment: C0805C476M9PAC7800)
C360  value 1µF  Voltage: 6.3V  Case Code (Imperial): 0201  [CAP-0201]  (hidden comment: GRM033R60J105MEA2D)
D4  SX34_R1_00001  Max Reverse Voltage (DC): 40V  Forward Current: 3A  [SMA DO214AC]
D9  SX34_R1_00001  Max Reverse Voltage (DC): 40V  Forward Current: 3A  [SMA DO214AC]
DL2  XHY-STB0603SR  [LEDC1608X80N-AK]
L10  SMNR5030-4R7MT  Tolerance: 20%  IRMS: 2.2A  Inductance: 4.7µH  [Inductor 5030]
R86  value 0  [RES-0201]  (hidden comment: CRCW02010000Z0ED)
R87  value 0  [RES-0201]  (hidden comment: CRCW02010000Z0ED)
R88  value 2M  Case Code (Imperial): 0402  [RES-0402]  (hidden comment: RC0402FR-072ML)
R89  value 2M  Case Code (Imperial): 0402  [RES-0402]  (hidden comment: RC0402FR-072ML)
R90  value 4.7k  [RES-0201]  (hidden comment: RC0201FR-074K7L)
R91  value 1k  [RES-0201]  (hidden comment: RC0201FR-071KL)
R92  value 1k  [RES-0201]  (hidden comment: RC0201FR-071KL)
R99  value 0  [RES-0201]  (hidden comment: CRCW02010000Z0ED)
R100  value 0  [RES-0201]  (hidden comment: CRCW02010000Z0ED)
R101  value 0  [RES-0201]  (hidden comment: CRCW02010000Z0ED)
R102  value 0  [RES-0201]  (hidden comment: CRCW02010000Z0ED)
R103  value 0  [RES-0201]  (hidden comment: CRCW02010000Z0ED)
R104  value 0  [RES-0201]  (hidden comment: CRCW02010000Z0ED)
R106  value 330  [RES-0201]  (hidden comment: AC0201FR-07330RL)
R113  value 0  [RES-0201]  (hidden comment: CRCW02010000Z0ED)
R114  value 0  [RES-0201]  (hidden comment: CRCW02010000Z0ED)
R161  value 0  [RES-0201]  (hidden comment: CRCW02010000Z0ED)
R172  value 10k  [RES-0201]  (hidden comment: RC0201FR-0710KL)
R173  value 10k  [RES-0201]  (hidden comment: RC0201FR-0710KL)
R178  value 0  [RES-0201]  (hidden comment: CRCW02010000Z0ED)
R186  value 0  [RES-0201]  (hidden comment: CRCW02010000Z0ED)
R187  value 0  [RES-0201]  (hidden comment: CRCW02010000Z0ED)
R234  value 24k  [RES-0201]  (hidden comment: RC0201FR-0724KL)
R235  value 0  [RES-0201]  (hidden comment: CRCW02010000Z0ED)
R236  value 24k  [RES-0201]  (hidden comment: RC0201FR-0724KL)
R237  value 0  [RES-0201]  (hidden comment: CRCW02010000Z0ED)
R244  value 100k  [RES-0201]  (hidden comment: RC0201FR-07100KL)
R246  value 220k  [RES-0201]  (hidden comment: AC0201FR-07220KL)
R247  value 220k  [RES-0201]  (hidden comment: AC0201FR-07220KL)
R271  value 24k  [RES-0201]  (hidden comment: RC0201FR-0724KL)
R274  value 0  [RES-0201]  (hidden comment: CRCW02010000Z0ED)
R275  value 0  [RES-0201]  (hidden comment: CRCW02010000Z0ED)
R276  value 0  Case Code (Imperial): 0805  [RES-0805]  (hidden comment: CRCW08050000Z0EB)
R324  value 10k  [RES-0201]  (hidden comment: RC0201FR-0710KL)
R325  value 10k  [RES-0201]  (hidden comment: RC0201FR-0710KL)
R330  value 1k  [RES-0201]  (hidden comment: RC0201FR-071KL)
R331  value 1k  [RES-0201]  (hidden comment: RC0201FR-071KL)
R332  value 1k  [RES-0201]  (hidden comment: RC0201FR-071KL)
R333  value 4.7k  [RES-0201]  (hidden comment: RC0201FR-074K7L)
R334  value 4.7k  [RES-0201]  (hidden comment: RC0201FR-074K7L)
R335  value 4.7k  [RES-0201]  (hidden comment: RC0201FR-074K7L)
R367  value 0  [RES-0201]  (hidden comment: CRCW02010000Z0ED)
R368  value 0  [RES-0201]  (hidden comment: CRCW02010000Z0ED)
R369  value 0  [RES-0201]  (hidden comment: CRCW02010000Z0ED)
R370  value 0  [RES-0201]  (hidden comment: CRCW02010000Z0ED)
R398  value 100k  Case Code (Imperial): 0402  [RES-0402]  (hidden comment: CRCW0402100KFKEDC)
R460  value 100k  Case Code (Imperial): 0402  [RES-0402]  (hidden comment: CRCW0402100KFKEDC)
R498  value 100k  Tolerance: 1%  Case Code (Imperial): 0201  [RES-0201]  (hidden comment: RC0201FR-07100KL)
R499  value 0  Case Code (Imperial): 0201  [RES-0201]  (hidden comment: CRCW02010000Z0ED)
R500  value 31.6k  Case Code (Imperial): 0201  Tolerance: 1%  Temperature Coefficient: 100ppm  [RES-0201]  (hidden comment: CRCW020131K6FKED)
R501  value 0  Case Code (Imperial): 0201  [RES-0201]  (hidden comment: CRCW02010000Z0ED)
R502  value 0  Case Code (Imperial): 0805  [RES-0805]  (hidden comment: CRCW08050000Z0EB)
R503  value 1k  Case Code (Imperial): 0201  [RES-0201]  (hidden comment: RC0201FR-071KL)
R504  value 0  Case Code (Imperial): 0201  [RES-0201]  (hidden comment: CRCW02010000Z0ED)
R505  value 0  Case Code (Imperial): 0805  [RES-0805]  (hidden comment: CRCW08050000Z0EB)
TP29  Test point 1.00mm  [TP-1.00MM]  (value not drawn)  (no BOM)
TP36  Test point 1.00mm  [TP-1.00MM]  (value not drawn)  (no BOM)
TP37  Test point 1.00mm  [TP-1.00MM]  (value not drawn)  (no BOM)
TP38  Test point 1.00mm  [TP-1.00MM]  (value not drawn)  (no BOM)
TP39  Test point 1.00mm  [TP-1.00MM]  (value not drawn)  (no BOM)
U5  CYPD6129-52LQXI  [QFN52 pitch 0.4mm, 5x8mm]
U26  LMR51440SDRRR  [WSON8 TI DDR 3x3mm 12 pins pitch 0.5mm]
U30  MP2013GG-Z  [MPS QNF6 2x2mm 6pin pitch 0.65mm thermal pad]

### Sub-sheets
T8CH_ = TRANSLATOR_8CH.SchDoc: 1V8_A1, 1V8_A2, 1V8_A3, 1V8_A4, 1V8_A5, 1V8_A6, 1V8_A7, 1V8_A8, 3V3_B1, 3V3_B2, 3V3_B3, 3V3_B4, 3V3_B5, 3V3_B6, 3V3_B7, 3V3_B8, VCCA, VCCB

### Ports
5V, GPIO0/RTM_RST/P0.0_3V3, GPIO1/P0.1_3V3, GPIO2/RTM_EN/P0.2_3V3, GPIO3/P0.3_3V3, GPIO4_1V8, GPIO5_1V8, GPIO7/DEBUG#/P3.1_3V3, GPIO8/PROCHOT#/P3.2_3V3, I2C1_1V8 (harness I2C), I2C1_IRQ/P0.4_1V8 (out), I2C2_3V3 (harness I2C), I2C2_IRQ/P2.0 (out), I2C3_3V3 (harness I2C), I2C_DBG_3V3 (harness I2C), PA_AUX_N, PA_AUX_P, PA_CC1, PA_CC2, PA_EXT (out), PA_SBRX, PA_SBTX, PA_SBU1, PA_SBU2, PA_VBUS (in), XRES_1V8 (in)

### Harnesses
I2C: SDA, SCL

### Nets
7V-24V: D9.A
+3V3: R275.1
+5V: R276.2 ; port 5V
CYPD_VDDIO: C46.2 C360.2 R90.1 R91.1 R271.2 R274.2 R333.1 R334.1 R335.1 R501.1 R502.2 TP29.X U5.31(VDDIO) ; sheet T8CH_/VCCB
GND: C40.1 C41.1 C42.1 C43.1 C44.2 C45.1 C46.1 C47.1 C48.1 C49.1 C84.1 C302.1 C303.2 C304.1 C308.1 C351.2 C352.2 C353.2 C354.2 C355.1 C356.2 C357.2 C359.1 C360.1 DL2.C R88.1 R89.1 R92.2 R172.1 R173.2 R247.2 R324.1 R325.2 R460.1 R499.1 R500.1 TP36.X U5.13(GND) U5.53(EPAD) U26.8(AGND) U26.13(PGND) U30.3(GND) U30.7(GND_PAD)
SOM_VREG_MDPX3_1P8: R330.1 R331.1 R332.1 ; sheet T8CH_/VCCA
EDP0_AUX_N: U5.35(PA_AUX_N) ; port PA_AUX_N
EDP0_AUX_P: U5.36(PA_AUX_P) ; port PA_AUX_P
GPIO4_SWDIO: TP39.X U5.27(GPIO4/LSTX_DIR_SEL/SWD_IO/P5.0) ; sheet T8CH_/3V3_B4
GPIO5_SWCLK: TP38.X U5.28(GPIO5/SWD_CLK/P5.1) ; sheet T8CH_/3V3_B5
I2C1_IRQ: R99.1 R333.2 ; sheet T8CH_/3V3_B1
I2C1_SCL: R100.1 R334.2 ; sheet T8CH_/3V3_B2
I2C1_SDA: R101.1 R335.2 ; sheet T8CH_/3V3_B3
MD_GPIO_3: R186.1 R330.2 ; port I2C1_IRQ/P0.4_1V8
MD_GPIO_45: R237.1 R332.2 ; port I2C1_1V8.SDA
MD_GPIO_46: R235.1 R331.2 ; port I2C1_1V8.SCL
MD_GPIO_48: R178.1 ; port GPIO5_1V8
MD_GPIO_94: R161.1 ; port GPIO4_1V8
MD_GPIO_104: R187.1 ; port XRES_1V8
PA_VBUS: D4.A U5.41(PA_VBUS) U5.42(PA_VBUS) ; port PA_VBUS
USBC_CC1: C40.2 U5.40(PA_CC1) ; port PA_CC1
USBC_CC2: C41.2 U5.39(PA_CC2) ; port PA_CC2
USBC_SBU1: R88.2 U5.38(PA_SBU1) ; port PA_SBU1
USBC_SBU2: R89.2 U5.37(PA_SBU2) ; port PA_SBU2
XRES: C49.2 R90.2 TP37.X U5.24(XRES) ; sheet T8CH_/3V3_B6
NetC42_2: C42.2 C43.2 U5.29(LDO1_(VCCD))
NetC44_1: C44.1 C45.2 U5.30(LDO2_(VDDD))
NetC47_2: C47.2 C48.2 R274.1 R275.2 U5.32(VIN_3V3_(VSYS))
NetC84_2: C84.2 R276.1 U5.46(5_V) U5.47(5_V) U5.48(5_V) U5.49(5_V)
NetC302_2: C302.2 C303.1 R504.1 U30.1(IN) U30.2(IN)
NetC304_2: C304.2 C308.2 R234.2 R501.2 U30.6(OUT)
NetC350_1: C350.1 U26.4(BOOT)
NetC350_2: C350.2 L10.1 U26.1(SW) U26.2(SW) U26.3(SW)
NetC351_1: C351.1 C352.1 C356.1 C357.1 R398.2 R505.1 U26.10(VIN) U26.11(VIN) U26.12(VIN)
NetC353_1: C353.1 R398.1 R460.2 U26.9(EN)
NetC354_1: C354.1 C355.2 C359.2 L10.2 R498.2 R502.1 R503.2
NetC358_1: C358.1 R503.1
NetC358_2: C358.2 R498.1 R500.2 U26.7(FB)
NetD4_C: D4.C D9.C R504.2 R505.2
NetDL2_A: DL2.A R106.1
NetQ3_2: R368.1 ; port GPIO3/P0.3_3V3
NetQ3_3: R367.1 ; port GPIO1/P0.1_3V3
NetR86_1: R86.1 ; port I2C2_IRQ/P2.0
NetR86_2: R86.2 U5.21(I2C2_IRQ/P2.0)
NetR87_1: R87.1 ; port I2C2_3V3.SCL
NetR87_2: R87.2 U5.22(I2C2_SCL/P2.1)
NetR91_2: R91.2 R92.1 U5.52(I2CADDR/P3.3)
NetR97_1: R102.1 ; port I2C3_3V3.SCL
NetR98_1: R103.1 ; port I2C3_3V3.SDA
NetR99_2: R99.2 U5.18(I2C1_IRQ/P0.4)
NetR100_2: R100.2 U5.19(I2C1_SCL/P1.0)
NetR101_2: R101.2 U5.20(I2C1_SDA/P1.1)
NetR102_2: R102.2 U5.25(I2C3_SCL/P2.3)
NetR103_2: R103.2 U5.26(I2C3_SDA/P2.4)
NetR104_1: R104.1 ; port I2C2_3V3.SDA
NetR104_2: R104.2 U5.23(I2C2_SDA/P2.2)
NetR106_2: R106.2 U5.51(GPIO9/P4.1)
NetR113_1: R113.1 ; port I2C_DBG_3V3.SDA
NetR113_2: R113.2 U5.11(PA_DBG_SDA)
NetR114_1: R114.1 ; port I2C_DBG_3V3.SCL
NetR114_2: R114.2 U5.12(PA_DBG_SCL)
NetR161_2: R161.2 ; sheet T8CH_/1V8_A4
NetR172_2: R172.2 ; sheet T8CH_/1V8_A7
NetR173_1: R173.1 ; sheet T8CH_/3V3_B7
NetR178_2: R178.2 ; sheet T8CH_/1V8_A5
NetR186_2: R186.2 ; sheet T8CH_/1V8_A1
NetR187_2: R187.2 ; sheet T8CH_/1V8_A6
NetR215_1: U5.43(PA_EXT/P4.0) ; port PA_EXT
NetR234_1: R234.1 R236.2
NetR235_2: R235.2 ; sheet T8CH_/1V8_A2
NetR236_1: R236.1 R244.2
NetR237_2: R237.2 ; sheet T8CH_/1V8_A3
NetR244_1: R244.1 R246.1
NetR246_2: R246.2 R247.1 U30.4(FB)
NetR271_1: R271.1 R367.2 U5.15(GPIO1/P0.1)
NetR324_2: R324.2 ; sheet T8CH_/1V8_A8
NetR325_1: R325.1 ; sheet T8CH_/3V3_B8
NetR368_2: R368.2 U5.17(GPIO3/P0.3)
NetR369_1: R369.1 ; port GPIO0/RTM_RST/P0.0_3V3
NetR369_2: R369.2 U5.14(GPIO0/RTM_RST/P0.0)
NetR370_1: R370.1 ; port GPIO2/RTM_EN/P0.2_3V3
NetR370_2: R370.2 U5.16(GPIO2/RTM_EN/P0.2)
NetR499_2: R499.2 U26.6(RT)
NetU5_33: U5.33(PA_SBRX) ; port PA_SBRX
NetU5_34: U5.34(PA_SBTX) ; port PA_SBTX
NetU5_45: U5.45(GPIO7/DEBUG#/P3.1) ; port GPIO7/DEBUG#/P3.1_3V3
NetU5_50: U5.50(GPIO8/PROCHOT#/P3.2) ; port GPIO8/PROCHOT#/P3.2_3V3

Not connected (* = marked no-connect by the designer): U5 1(NC)* 2(NC)* 3(NC)* 4(NC)* 5(NC)* 6(NC)* 7(NC)* 8(NC)* 9(NC)* 10(NC)* 44(GPIO6/FAULT#/P3.0)*; U26 5(PG)*; U30 5(NC)*

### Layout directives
net class HIGH_CLEARANCE: NetC302_2, NetC351_1, NetD4_C

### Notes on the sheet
- FAULT LED
- (near DL2) FAULT LED RED
- 3V3 LOCAL LDO
- 3V3 LOCAL DCDC

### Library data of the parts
C40 C41 = C0197-A.2: CAP CHIP 0402 390pF 10% 50V X7R; Manufacturer: Murata; Code Arduino: C0197
C42 C48 C304 C308 C360 = C0002-A.15: CAP CHIP 0201 1uF 20% 6.3V X5R; Manufacturer: Murata; Code Arduino: A5520
C43 C45-C47 C49 = C0113-A.6: as C54-C60 on sheet USB_MUX
C44 = C0037-A.14: CAP CHIP 0402 4.7uF 20% 6V3 X5R; Manufacturer: Hottech; Code Arduino: 0833
C84 C303 C350 C351 C353 C354 = C0015-A.14: CAP CHIP 0402 100nF 10% 50V X5R; Manufacturer: Murata; Code Arduino: A5141
C302 C352 C356 C357 = C0158-A.3: CAP CHIP 0805 10uF 20% 50V X5R; Manufacturer: Murata Electronics; Code Arduino: C0158
C355 C359 = C0199-A.1: as C35 on sheet USB
C358 = C0115-A.6: CAP CHIP 0201 22pF 5% 25V C0G; Manufacturer: Yageo; Code Arduino: C0115
D4 D9 = D0109-A.2: DIODE SCHOTTKY SMD 3A 40V SMA DO214AC; Part Number: SX34-AU_R1_000A1; Manufacturer: Panjit; Code Arduino: D0109; Forward Voltage: 0.39V
DL2 = L0024-A.4: LED SMD 0603 RED 625nm, water clear, 42 to 88 mcd, 120 degrees, 1.6x0.8x0.6mm; Manufacturer: Shenzen Corehy Technology; Code Arduino: L0024
L10 = I0133-A.2: IND SMD 4.7uH 20%, DCR max 65mR, I sat 3A, I RMS 2.2A, package 5x5mm height 3mm; Manufacturer: Shun Xiang Nuo; DCR max: 65m; Code Arduino: I0133
R86 R87 R99-R104 R113 R114 R161 R178 R186 R187 R235 R237 R274 R275 R367-R370 R499 R501 R504 = R0140-A.21: as R94 on sheet USB_MUX
R88 R89 = R0394-A.1: RES CHIP 0402 2M 1% 1/16W; Manufacturer: YAGEO; Temperature coefficient: 100ppm; Code Arduino: R0394; Power: 62.5mW
R90 R333-R335 = R0151-A.21: RES CHIP 0201 4k7 1% 1/20W; Manufacturer: Yageo; Power: 50mW; Temperature coefficient: 200ppm; Code Arduino: A5521
R91 R92 R330-R332 R503 = R0195-A.22: RES CHIP 0201 1k 1% 1/20W; Manufacturer: Yageo; Power: 50mW; Temperature coefficient: 200ppm; Code Arduino: R0195
R106 = R0149-A.21: RES CHIP 0201 330R 1% 1/20W; Manufacturer: Yageo; Power: 50mW; Code Arduino: R0149; Temperature coefficient: 200ppm
R172 R173 R324 R325 = R0145-A.21: as R154 on sheet USB
R234 R236 R271 = R0398-A.1: as R25 on sheet USB
R244 = R0146-A.21: RES CHIP 0201 100k 1% 1/20W; Manufacturer: Yageo; Power: 50mW; Temperature coefficient: 200ppm; Code Arduino: R0146
R246 R247 = R0199-A.20: as R436 on sheet USB
R276 R502 R505 = R0131-A.13: RES CHIP 0805 0R; Manufacturer: Vishay; Temperature coefficient: 0ppm; Code Arduino: A5394; Power: 125mW; Tolerance: 0%
R398 R460 = R0001-A.24: RES CHIP 0402 100k 1% 1/16W; Manufacturer: Vishay; Code Arduino: 0134; Temperature coefficient: 100ppm; Power: 62.5mW
R498 = R0146-A.21: RES CHIP 0201 100k 1% 1/20W; Manufacturer: Yageo; Code Arduino: R0146; Temperature coefficient: 200ppm; Power: 50mW
R500 = R0420-A.1: RES CHIP 0201 31k6 1% 1/20W 100ppm; Manufacturer: Vishay; Power: 50mW; Code Arduino: R0420
TP29 TP36-TP39 = UT0013-A.6: Part Number: This is not a component
U5 = U0495-A.3: IC Controller power delivery USB-C, QFN52 5x8mm; Manufacturer: Infineon; Code Arduino: U0495
U26 = U0467-A.1: IC BUCK Vin 4-36V, Iout 4A, max duty 97%, fsw 1.1MHz, WSON8 3x3mm; Manufacturer: Texas Instruments; Code Arduino: U0467
U30 = U0518-A.2: IC LDO, Vin 2.5V-40V, Vout ADJ, Iout 0.15A, Iq typ 15uA, QFN6 2x2mm; Manufacturer: MPS; Code Arduino: U0518

## Sheet TRANSLATOR_8CH.SchDoc: TRANSLATOR 8CH
size A4; Author: Silvio Navaretti; CompanyName: ARDUINO; DrawnBy: Silvio Navaretti; Engineer: Silvio Navaretti; Organization: ARDUINO; SheetNumber: 51; SheetTotal: 51; RevAuthor: Silvio Navaretti
Used 5 times, as channels U_USB/U_USB_PD_CONTROLLER/T8CH_, U_HEADERS_JHAT/T8CH_, U_HEADERS_JHAT/T8CH_, U_HEADERS_JHAT/T8CH_, T8CH_. Parts and nets are listed once, with the designators drawn on the sheet.
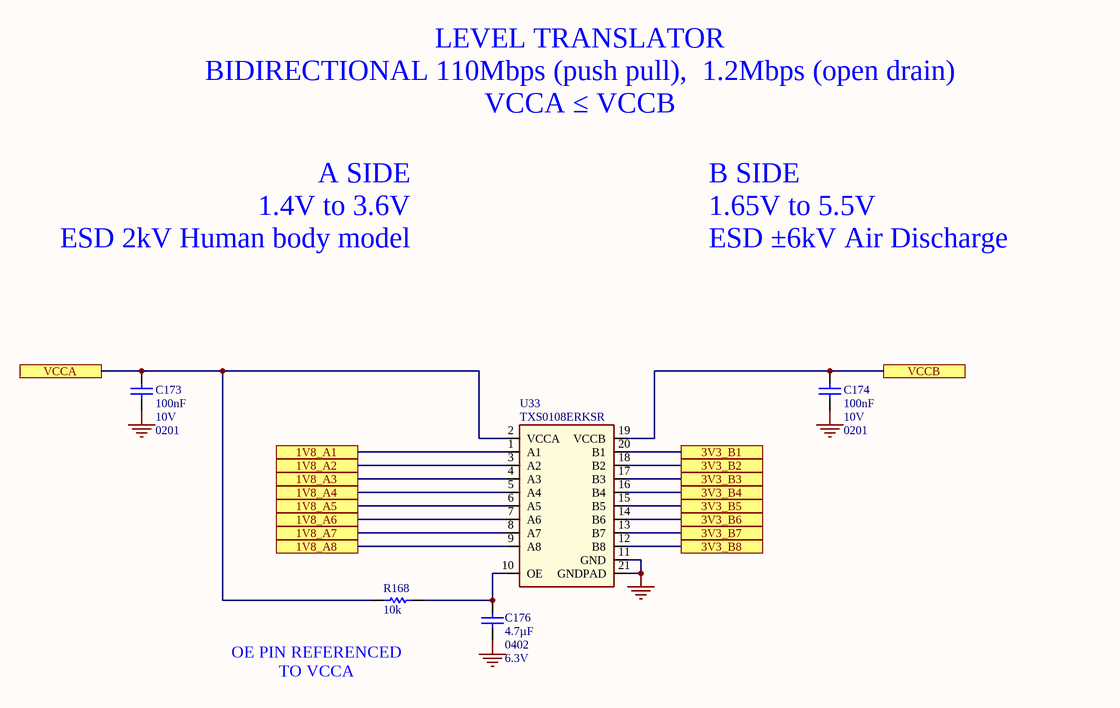
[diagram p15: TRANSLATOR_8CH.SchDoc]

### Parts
C173  value 100nF  Voltage: 10V  Case Code (Imperial): 0201  [CAP-0201]  (hidden comment: CL03A104KP3NNNC)
C174  value 100nF  Voltage: 10V  Case Code (Imperial): 0201  [CAP-0201]  (hidden comment: CL03A104KP3NNNC)
C176  value 4.7µF  Case Code (Imperial): 0402  Voltage: 6.3V  [CAP-0402]  (hidden comment: C1005A475M6R3NT)
R168  value 10k  [RES-0201]  (hidden comment: RC0201FR-0710KL)
U33  TXS0108ERKSR  [QFN50P250X450X100_HS-21N]

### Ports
1V8_A1, 1V8_A2, 1V8_A3, 1V8_A4, 1V8_A5, 1V8_A6, 1V8_A7, 1V8_A8, 3V3_B1, 3V3_B2, 3V3_B3, 3V3_B4, 3V3_B5, 3V3_B6, 3V3_B7, 3V3_B8, VCCA, VCCB

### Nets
GND: C173.1 C174.1 C176.2 U33.11(GND) U33.21(GNDPAD)
1V8_A1: U33.1(A1) ; port 1V8_A1
1V8_A2: U33.3(A2) ; port 1V8_A2
1V8_A3: U33.4(A3) ; port 1V8_A3
1V8_A4: U33.5(A4) ; port 1V8_A4
1V8_A5: U33.6(A5) ; port 1V8_A5
1V8_A6: U33.7(A6) ; port 1V8_A6
1V8_A7: U33.8(A7) ; port 1V8_A7
1V8_A8: U33.9(A8) ; port 1V8_A8
3V3_B1: U33.20(B1) ; port 3V3_B1
3V3_B2: U33.18(B2) ; port 3V3_B2
3V3_B3: U33.17(B3) ; port 3V3_B3
3V3_B4: U33.16(B4) ; port 3V3_B4
3V3_B5: U33.15(B5) ; port 3V3_B5
3V3_B6: U33.14(B6) ; port 3V3_B6
3V3_B7: U33.13(B7) ; port 3V3_B7
3V3_B8: U33.12(B8) ; port 3V3_B8
VCCA: C173.2 R168.2 U33.2(VCCA) ; port VCCA
VCCB: C174.2 U33.19(VCCB) ; port VCCB
NetC176_1: C176.1 R168.1 U33.10(OE)

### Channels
U_USB/U_USB_PD_CONTROLLER/T8CH_: designators end in _1; ports 1V8_A1=NetR186_2 1V8_A2=NetR235_2 1V8_A3=NetR237_2 1V8_A4=NetR161_2 1V8_A5=NetR178_2 1V8_A6=NetR187_2 1V8_A7=NetR172_2 1V8_A8=NetR324_2 3V3_B1=I2C1_IRQ 3V3_B2=I2C1_SCL 3V3_B3=I2C1_SDA 3V3_B4=GPIO4_SWDIO 3V3_B5=GPIO5_SWCLK 3V3_B6=XRES 3V3_B7=NetR173_1 3V3_B8=NetR325_1 VCCA=SOM_VREG_MDPX3_1P8 VCCB=CYPD_VDDIO
U_HEADERS_JHAT/T8CH_: designators end in _2; ports 1V8_A1=MD_GPIO_109 1V8_A2=I2S_SCK 1V8_A3=MD_GPIO_85 1V8_A4=MD_GPIO_87 1V8_A5=MD_GPIO_83 1V8_A6=MD_GPIO_86 1V8_A7=MD_GPIO_18 1V8_A8=MD_GPIO_17 3V3_B1=JHAT_GPIO_27 3V3_B2=JHAT_GPIO_18 3V3_B3=JHAT_GPIO_17 3V3_B4=JHAT_GPIO_15 3V3_B5=JHAT_GPIO_4 3V3_B6=JHAT_GPIO_14 3V3_B7=JHAT_GPIO_3 3V3_B8=JHAT_GPIO_2 VCCA=SOM_VREG_MDPX3_1P8 VCCB=+3V3_LIMITED
U_HEADERS_JHAT/T8CH_: designators end in _3; ports 1V8_A1=MD_GPIO_28 1V8_A2=MD_GPIO_107 1V8_A3=MD_GPIO_27 1V8_A4=MD_GPIO_25 1V8_A5=MD_GPIO_106 1V8_A6=MD_GPIO_26 1V8_A7=MD_GPIO_105 1V8_A8=MD_GPIO_90 3V3_B1=JHAT_GPIO_8 3V3_B2=JHAT_GPIO_25 3V3_B3=JHAT_GPIO_11 3V3_B4=JHAT_GPIO_9 3V3_B5=JHAT_GPIO_24 3V3_B6=JHAT_GPIO_10 3V3_B7=JHAT_GPIO_23 3V3_B8=JHAT_GPIO_22 VCCA=SOM_VREG_MDPX3_1P8 VCCB=+3V3_LIMITED
U_HEADERS_JHAT/T8CH_: designators end in _4; ports 1V8_A1=I2S_WS 1V8_A2=MD_GPIO_81 1V8_A3=MD_GPIO_77 1V8_A4=MD_GPIO_80 1V8_A5=MD_GPIO_89 1V8_A6=MD_GPIO_20 1V8_A7=MD_GPIO_19 1V8_A8=MD_GPIO_88 3V3_B1=JHAT_GPIO_19 3V3_B2=JHAT_GPIO_13 3V3_B3=JHAT_GPIO_12 3V3_B4=JHAT_GPIO_6 3V3_B5=JHAT_GPIO_5 3V3_B6=JHAT_GPIO_1 3V3_B7=JHAT_GPIO_0 3V3_B8=JHAT_GPIO_7 VCCA=SOM_VREG_MDPX3_1P8 VCCB=+3V3_LIMITED
T8CH_: designators end in _5; ports 1V8_A1=MD_GPIO_46 1V8_A2=MD_GPIO_45 1V8_A3=MD_CCI_I2C0.SCL 1V8_A4=MD_CCI_I2C0.SDA 1V8_A5=MD_CCI_I2C2.SCL 1V8_A6=MD_CCI_I2C2.SDA 1V8_A7=MD_CCI_I2C4.SCL 1V8_A8=MD_CCI_I2C4.SDA 3V3_B1=MD_QUP1_SE4_I2C_3V3.SCL 3V3_B2=MD_QUP1_SE4_I2C_3V3.SDA 3V3_B3=MD_CCI_I2C0_3V3.SCL 3V3_B4=MD_CCI_I2C0_3V3.SDA 3V3_B5=MD_CCI_I2C2_3V3.SCL 3V3_B6=MD_CCI_I2C2_3V3.SDA 3V3_B7=MD_CCI_I2C4_3V3.SCL 3V3_B8=MD_CCI_I2C4_3V3.SDA VCCA=SOM_VREG_MDPX3_1P8 VCCB=+3V3

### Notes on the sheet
- LEVEL TRANSLATOR
  BIDIRECTIONAL 110Mbps (push pull),  1.2Mbps (open drain)
  VCCA ≤ VCCB
- A SIDE
  1.4V to 3.6V
  ESD 2kV Human body model
- B SIDE
  1.65V to 5.5V
  ESD ±6kV Air Discharge
- (near R168) OE PIN REFERENCED TO VCCA

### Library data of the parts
C173 C174 = C0113-A.6: as C54-C60 on sheet USB_MUX
C176 = C0037-A.14: as C44 on sheet USB_PD_CONTROLLER
R168 = R0145-A.21: as R154 on sheet USB
U33 = U0456-A.4: IC TRANSLATOR LEVEL SHIFTER BIDIR 8b, push pull 110Mbps, open drain 1.2Mbps, VCCA 1.4V-3.6V, VCCB 1.6V-5.5V, VCCA≤VCCB, Output Enable, VQFN-20; Manufacturer: Texas Instruments; Code Arduino: U0456

## Sheet USB_USBA.SchDoc: USBA
size A3; Author: Silvio Navaretti; CompanyName: ARDUINO; DrawnBy: Silvio Navaretti; Engineer: Silvio Navaretti; Organization: ARDUINO; SheetNumber: 34; SheetTotal: 51; RevAuthor: Silvio Navaretti
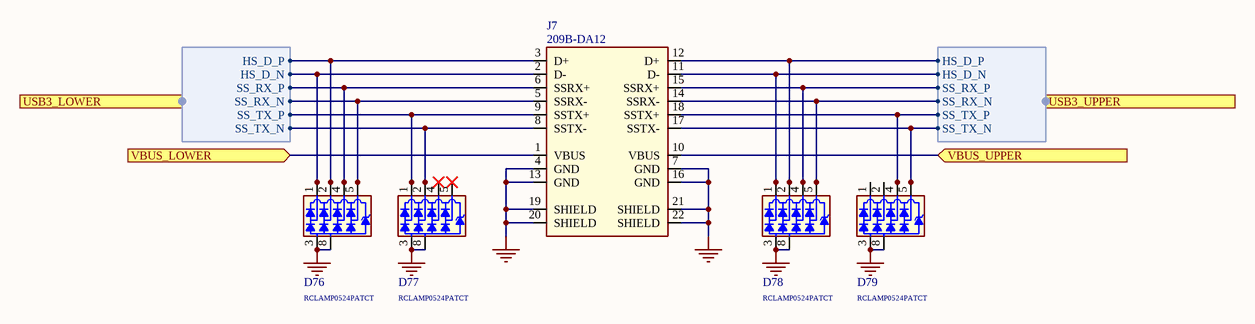
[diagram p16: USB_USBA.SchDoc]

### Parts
D76  RCLAMP0524PATCT  [SLP2510P8]
D77  RCLAMP0524PATCT  [SLP2510P8]
D78  RCLAMP0524PATCT  [SLP2510P8]
D79  RCLAMP0524PATCT  [SLP2510P8]
J7  209B-DA12  [209B-DA12]

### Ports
USB3_LOWER (harness SOM_MD_USB0), USB3_UPPER (harness SOM_MD_USB0), VBUS_LOWER (in), VBUS_UPPER (in)

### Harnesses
SOM_MD_USB0: SS_TX_N, SS_TX_P, HS_D_P, HS_D_N, SS_RX_P, SS_RX_N

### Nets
GND: D76.3 D76.8 D77.3 D77.8 D78.3 D78.8 D79.3 D79.8 J7.4(GND) J7.7(GND) J7.13(GND) J7.16(GND) J7.19(SHIELD) J7.20(SHIELD) J7.21(SHIELD) J7.22(SHIELD)
USB2_CAP_SSTX_N: D79.5 D79.6 J7.17(SSTX-) ; port USB3_UPPER.SS_TX_N
USB2_CAP_SSTX_P: D79.4 D79.7 J7.18(SSTX+) ; port USB3_UPPER.SS_TX_P
USB2_D_N: D78.1 D78.10 J7.11(D-) ; port USB3_UPPER.HS_D_N
USB2_D_P: D78.2 D78.9 J7.12(D+) ; port USB3_UPPER.HS_D_P
USB2_SSRX_N: D78.5 D78.6 J7.14(SSRX-) ; port USB3_UPPER.SS_RX_N
USB2_SSRX_P: D78.4 D78.7 J7.15(SSRX+) ; port USB3_UPPER.SS_RX_P
USB4_CAP_SSTX_N: D77.2 D77.9 J7.8(SSTX-) ; port USB3_LOWER.SS_TX_N
USB4_CAP_SSTX_P: D77.1 D77.10 J7.9(SSTX+) ; port USB3_LOWER.SS_TX_P
USB4_D_N: D76.1 D76.10 J7.2(D-) ; port USB3_LOWER.HS_D_N
USB4_D_P: D76.2 D76.9 J7.3(D+) ; port USB3_LOWER.HS_D_P
USB4_SSRX_N: D76.5 D76.6 J7.5(SSRX-) ; port USB3_LOWER.SS_RX_N
USB4_SSRX_P: D76.4 D76.7 J7.6(SSRX+) ; port USB3_LOWER.SS_RX_P
NetC35_2: J7.10(VBUS) ; port VBUS_UPPER
NetC147_2: J7.1(VBUS) ; port VBUS_LOWER
NetD77_4: D77.4 D77.7
NetD77_5: D77.5 D77.6
NetD79_1: D79.1 D79.10
NetD79_2: D79.2 D79.9

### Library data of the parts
D76-D79 = D0097-A.6: as D72 on sheet USB_USBC
J7 = J0560-A.4: CONN TH USB-A x2 stacked USB3.0 tab blue; Manufacturer: ATTEND; Code Arduino: J0560

## Sheet LOAD_SWITCH_5V.SchDoc: LOAD SWITCH 5V
size A3; Author: Silvio Navaretti; CompanyName: ARDUINO; DrawnBy: Silvio Navaretti; Engineer: Silvio Navaretti; Organization: ARDUINO; SheetNumber: 28; SheetTotal: 51; RevAuthor: Silvio Navaretti
Used 6 times, as channels U_USB/U_LOAD_SWITCH_5V, U_USB/U_LOAD_SWITCH_5V, U_ETH/U_ETH_PHY/U_LOAD_SWITCH_5V, U_POWER/U_LOAD_SWITCH_5V, U_POWER/U_LOAD_SWITCH_5V, U_PCIE/U_PCIE_NVME/U_LOAD_SWITCH_5V. Parts and nets are listed once, with the designators drawn on the sheet.
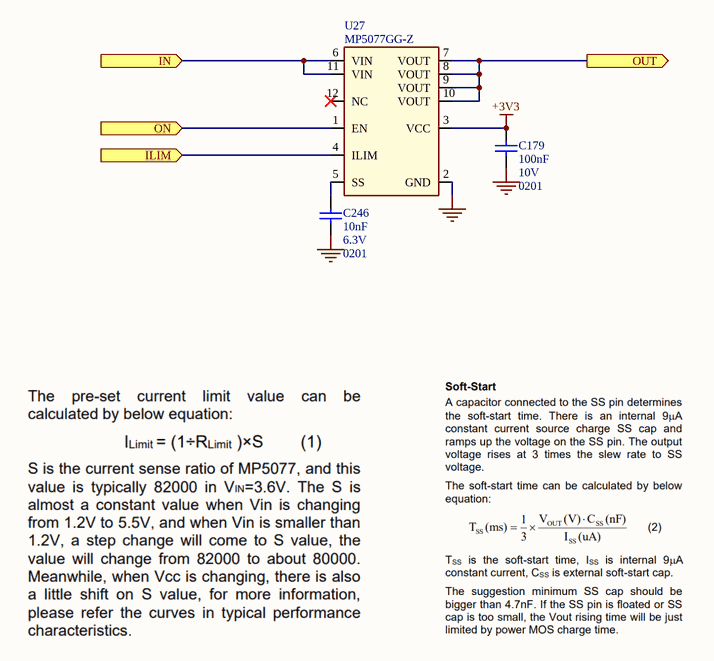
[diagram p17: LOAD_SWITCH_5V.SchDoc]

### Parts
C179  value 100nF  Voltage: 10V  Case Code (Imperial): 0201  [CAP-0201]  (hidden comment: CL03A104KP3NNNC)
C246  value 10nF  Voltage: 6.3V  Case Code (Imperial): 0201  [CAP-0201]  (hidden comment: GRM033R70J103KA01D)
U27  MP5077GG-Z  [MPS QFN12 2x2mm pitch 0.4mm]

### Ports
ILIM (in), IN (in), ON (in), OUT (out)

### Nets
+3V3: C179.2 U27.3(VCC)
GND: C179.1 C246.1 U27.2(GND)
ILIM: U27.4(ILIM) ; port ILIM
IN: U27.6(VIN) U27.11(VIN) ; port IN
ON: U27.1(EN) ; port ON
OUT: U27.7(VOUT) U27.8(VOUT) U27.9(VOUT) U27.10(VOUT) ; port OUT
NetC246_2: C246.2 U27.5(SS)

Not connected (* = marked no-connect by the designer): U27 12(NC)*

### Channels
U_USB/U_LOAD_SWITCH_5V: designators end in _1; ports ILIM=NetR25_2 IN=+5V ON=NetR182_2 OUT=NetC35_2
U_USB/U_LOAD_SWITCH_5V: designators end in _2; ports ILIM=NetR26_2 IN=+5V ON=NetR154_2 OUT=NetC147_2
U_ETH/U_ETH_PHY/U_LOAD_SWITCH_5V: designators end in _3; ports ILIM=NetR342_2 IN=+1V8 ON=NetC36_2 OUT=DVDD18
U_POWER/U_LOAD_SWITCH_5V: designators end in _4; ports ILIM=NetR339_2 IN=+5V ON=NetR336_2 OUT=+5V_LIMITED
U_POWER/U_LOAD_SWITCH_5V: designators end in _5; ports ILIM=NetR341_2 IN=+3V3 ON=NetR337_2 OUT=+3V3_LIMITED
U_PCIE/U_PCIE_NVME/U_LOAD_SWITCH_5V: designators end in _6; ports ILIM=NetR183_2 IN=+3V3 ON=MD_GPIO_51 OUT=NetC224_2

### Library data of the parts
C179 = C0113-A.6: as C54-C60 on sheet USB_MUX
C246 = C0112-A.6: CAP CHIP 0201 10nF 10% 6.3V X7R; Manufacturer: Murata; Code Arduino: C0112
U27 = U0512-A.2: IC Load Switch Vload 0.5V to 5.5V, 10mR at 5V, max 7A, programmable overcurrent limit, linear ramp control, logic ON 1.7V, VCC 3V to 5.5V, -40 to 125°C, QFN12 2x2mm; Manufacturer: MPS; Code Arduino: U0512

## Sheet ETH.SchDoc: ETH
size A3; Author: Silvio Navaretti; CompanyName: ARDUINO; DrawnBy: Silvio Navaretti; Engineer: Silvio Navaretti; Organization: ARDUINO; SheetNumber: 35; SheetTotal: 50; RevAuthor: Silvio Navaretti
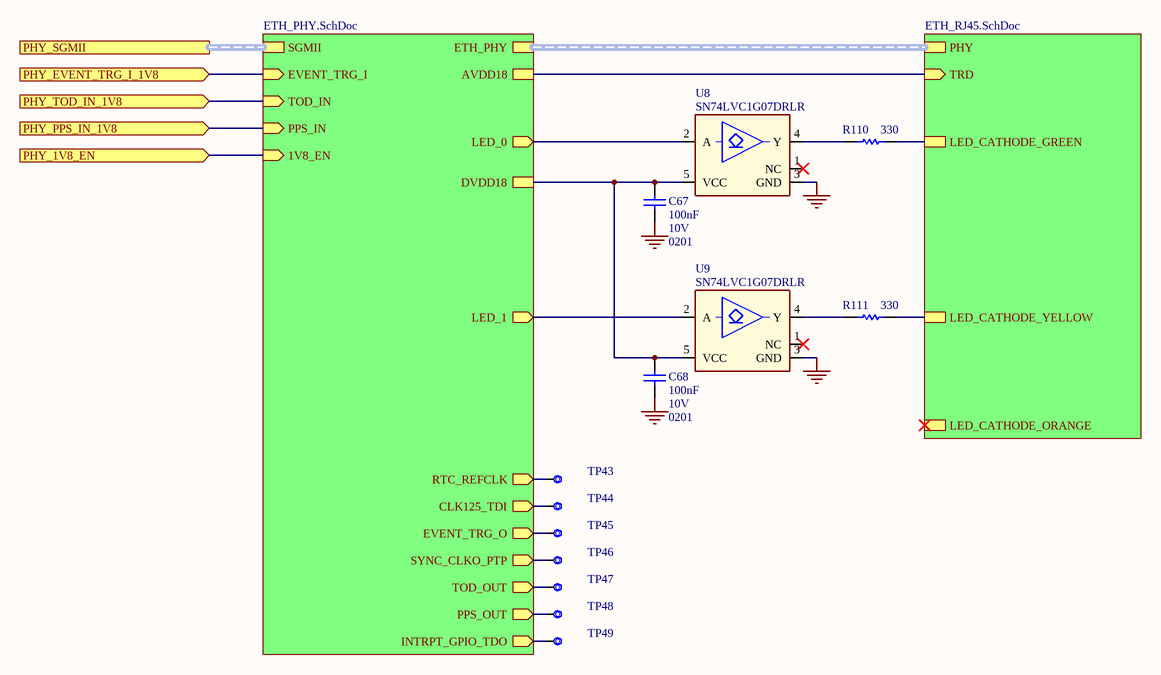
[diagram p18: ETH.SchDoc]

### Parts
C67  value 100nF  Voltage: 10V  Case Code (Imperial): 0201  [CAP-0201]  (hidden comment: CL03A104KP3NNNC)
C68  value 100nF  Voltage: 10V  Case Code (Imperial): 0201  [CAP-0201]  (hidden comment: CL03A104KP3NNNC)
R110  value 330  [RES-0201]  (hidden comment: AC0201FR-07330RL)
R111  value 330  [RES-0201]  (hidden comment: AC0201FR-07330RL)
TP43  Test point 1.00mm  [TP-1.00MM]  (value not drawn)  (no BOM)
TP44  Test point 1.00mm  [TP-1.00MM]  (value not drawn)  (no BOM)
TP45  Test point 1.00mm  [TP-1.00MM]  (value not drawn)  (no BOM)
TP46  Test point 1.00mm  [TP-1.00MM]  (value not drawn)  (no BOM)
TP47  Test point 1.00mm  [TP-1.00MM]  (value not drawn)  (no BOM)
TP48  Test point 1.00mm  [TP-1.00MM]  (value not drawn)  (no BOM)
TP49  Test point 1.00mm  [TP-1.00MM]  (value not drawn)  (no BOM)
U8  SN74LVC1G07DRLR  [TI DRL DRL0005A]
U9  SN74LVC1G07DRLR  [TI DRL DRL0005A]

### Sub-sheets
U_ETH_PHY = ETH_PHY.SchDoc: ETH_PHY (harness ETH_QCA8081), SGMII (harness SOM_MD_SGMII0), LED_0 (out), LED_1 (out), CLK125_TDI (out), EVENT_TRG_O (out), SYNC_CLKO_PTP (out), TOD_OUT (out), PPS_OUT (out), EVENT_TRG_I (in), INTRPT_GPIO_TDO (out), PPS_IN (in), RTC_REFCLK (out), TOD_IN (in), AVDD18, 1V8_EN (in), DVDD18
U_ETH_RJ45 = ETH_RJ45.SchDoc: LED_CATHODE_GREEN, LED_CATHODE_ORANGE, LED_CATHODE_YELLOW, PHY (harness ETH_QCA8081), TRD (in)

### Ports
PHY_1V8_EN (in), PHY_EVENT_TRG_I_1V8 (in), PHY_PPS_IN_1V8 (in), PHY_SGMII, PHY_TOD_IN_1V8 (in)

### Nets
GND: C67.1 C68.1 U8.3(GND) U9.3(GND)
1V05_PG (PULLUP 1V8): port PHY_1V8_EN, sheet U_ETH_PHY/1V8_EN
DVDD18: C67.2 C68.2 U8.5(VCC) U9.5(VCC) ; sheet U_ETH_PHY/DVDD18
NetC12_2: sheet U_ETH_PHY/AVDD18, sheet U_ETH_RJ45/TRD
NetJ2_13: R111.1 ; sheet U_ETH_RJ45/LED_CATHODE_YELLOW
NetJ2_17: R110.1 ; sheet U_ETH_RJ45/LED_CATHODE_GREEN
NetR62_1: TP45.X ; sheet U_ETH_PHY/EVENT_TRG_O
NetR63_1: TP44.X ; sheet U_ETH_PHY/CLK125_TDI
NetR64_1: TP46.X ; sheet U_ETH_PHY/SYNC_CLKO_PTP
NetR65_1: TP47.X ; sheet U_ETH_PHY/TOD_OUT
NetR66_1: U9.2(A) ; sheet U_ETH_PHY/LED_1
NetR67_1: U8.2(A) ; sheet U_ETH_PHY/LED_0
NetR68_1: TP48.X ; sheet U_ETH_PHY/PPS_OUT
NetR110_2: R110.2 U8.4(Y)
NetR111_2: R111.2 U9.4(Y)
NetTP40_X: port PHY_EVENT_TRG_I_1V8, sheet U_ETH_PHY/EVENT_TRG_I
NetTP41_X: port PHY_TOD_IN_1V8, sheet U_ETH_PHY/TOD_IN
NetTP42_X: port PHY_PPS_IN_1V8, sheet U_ETH_PHY/PPS_IN
NetTP43_X: TP43.X ; sheet U_ETH_PHY/RTC_REFCLK
NetTP49_X: TP49.X ; sheet U_ETH_PHY/INTRPT_GPIO_TDO

Not connected (* = marked no-connect by the designer): U8 1(NC)*; U9 1(NC)*

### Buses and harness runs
harness port PHY_SGMII = sheet U_ETH_PHY/SGMII
harness sheet U_ETH_PHY/ETH_PHY = sheet U_ETH_RJ45/PHY

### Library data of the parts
C67 C68 = C0113-A.6: as C54-C60 on sheet USB_MUX
R110 R111 = R0149-A.21: RES CHIP 0201 330R 1% 1/20W; Manufacturer: Yageo; Code Arduino: R0149; Power: 50mW; Temperature coefficient: 200ppm
TP43-TP49 = UT0013-A.6: Part Number: This is not a component
U8 U9 = U0494-A.2: IC buffer open drain, 1.65V to 5.5V, 32mA sink current, SOT-5X3 1.6mmx1.6mm; Manufacturer: Texas Instruments; Code Arduino: U0494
